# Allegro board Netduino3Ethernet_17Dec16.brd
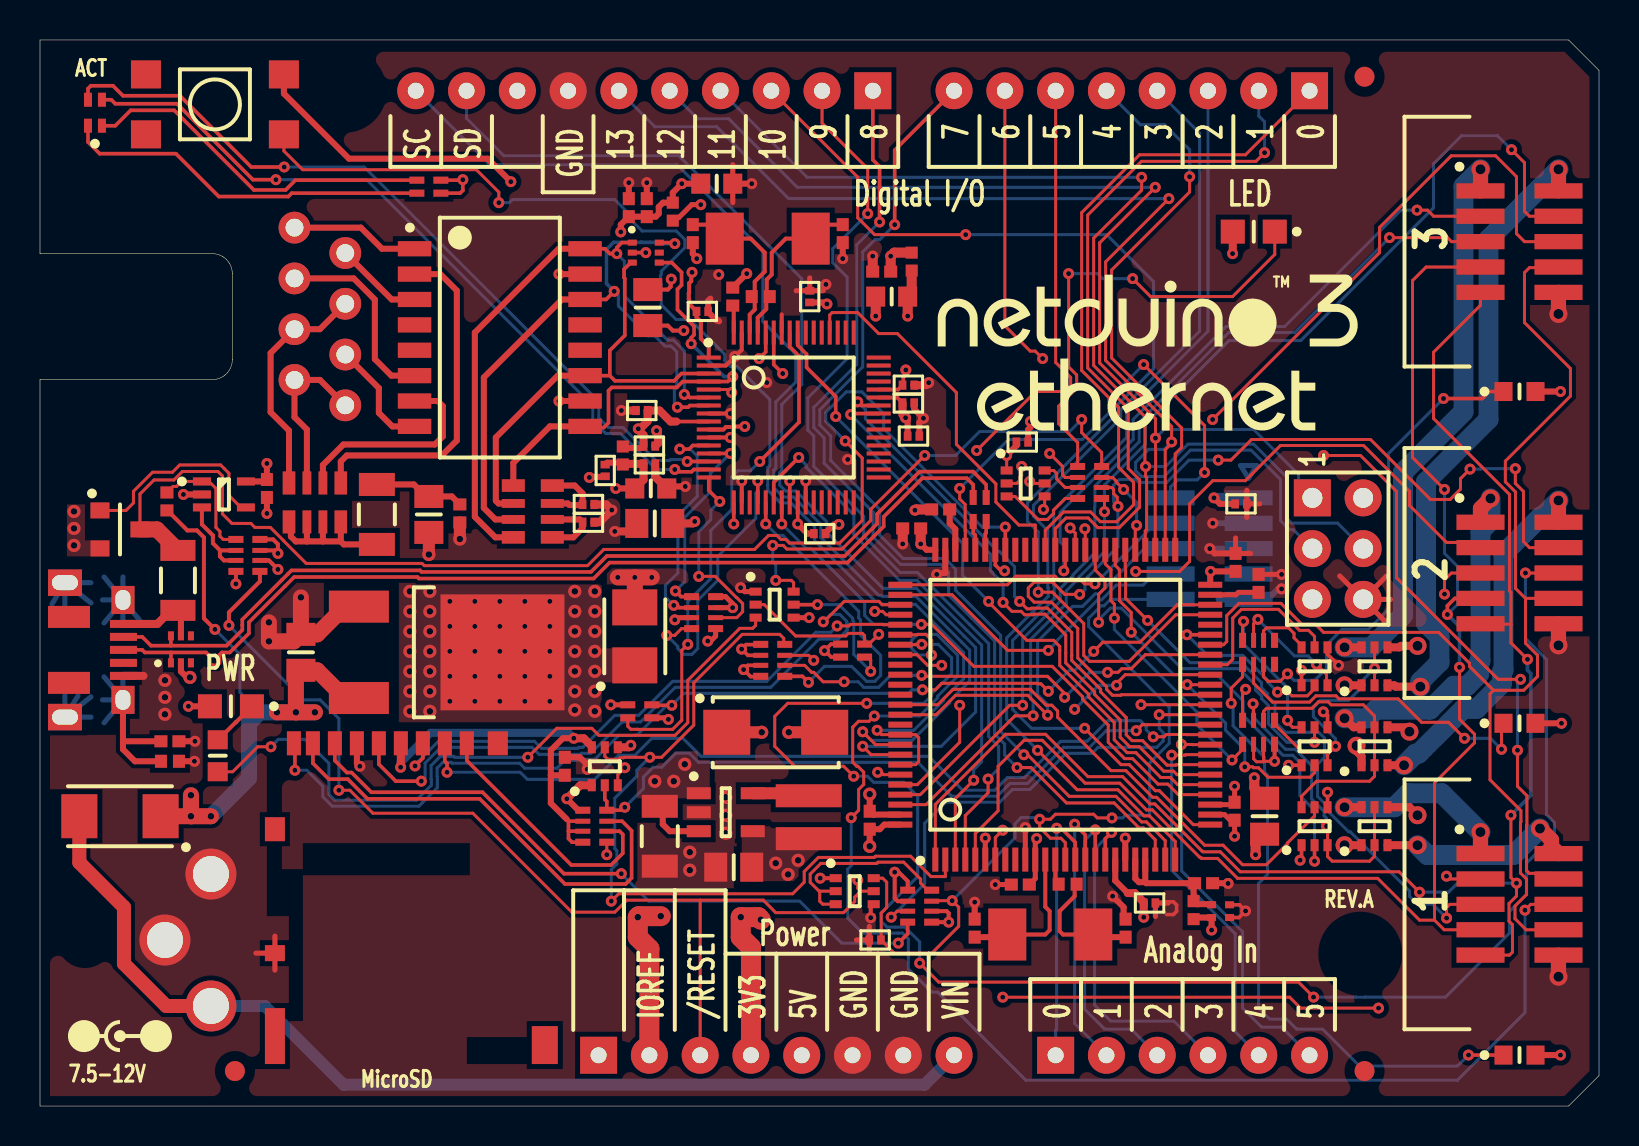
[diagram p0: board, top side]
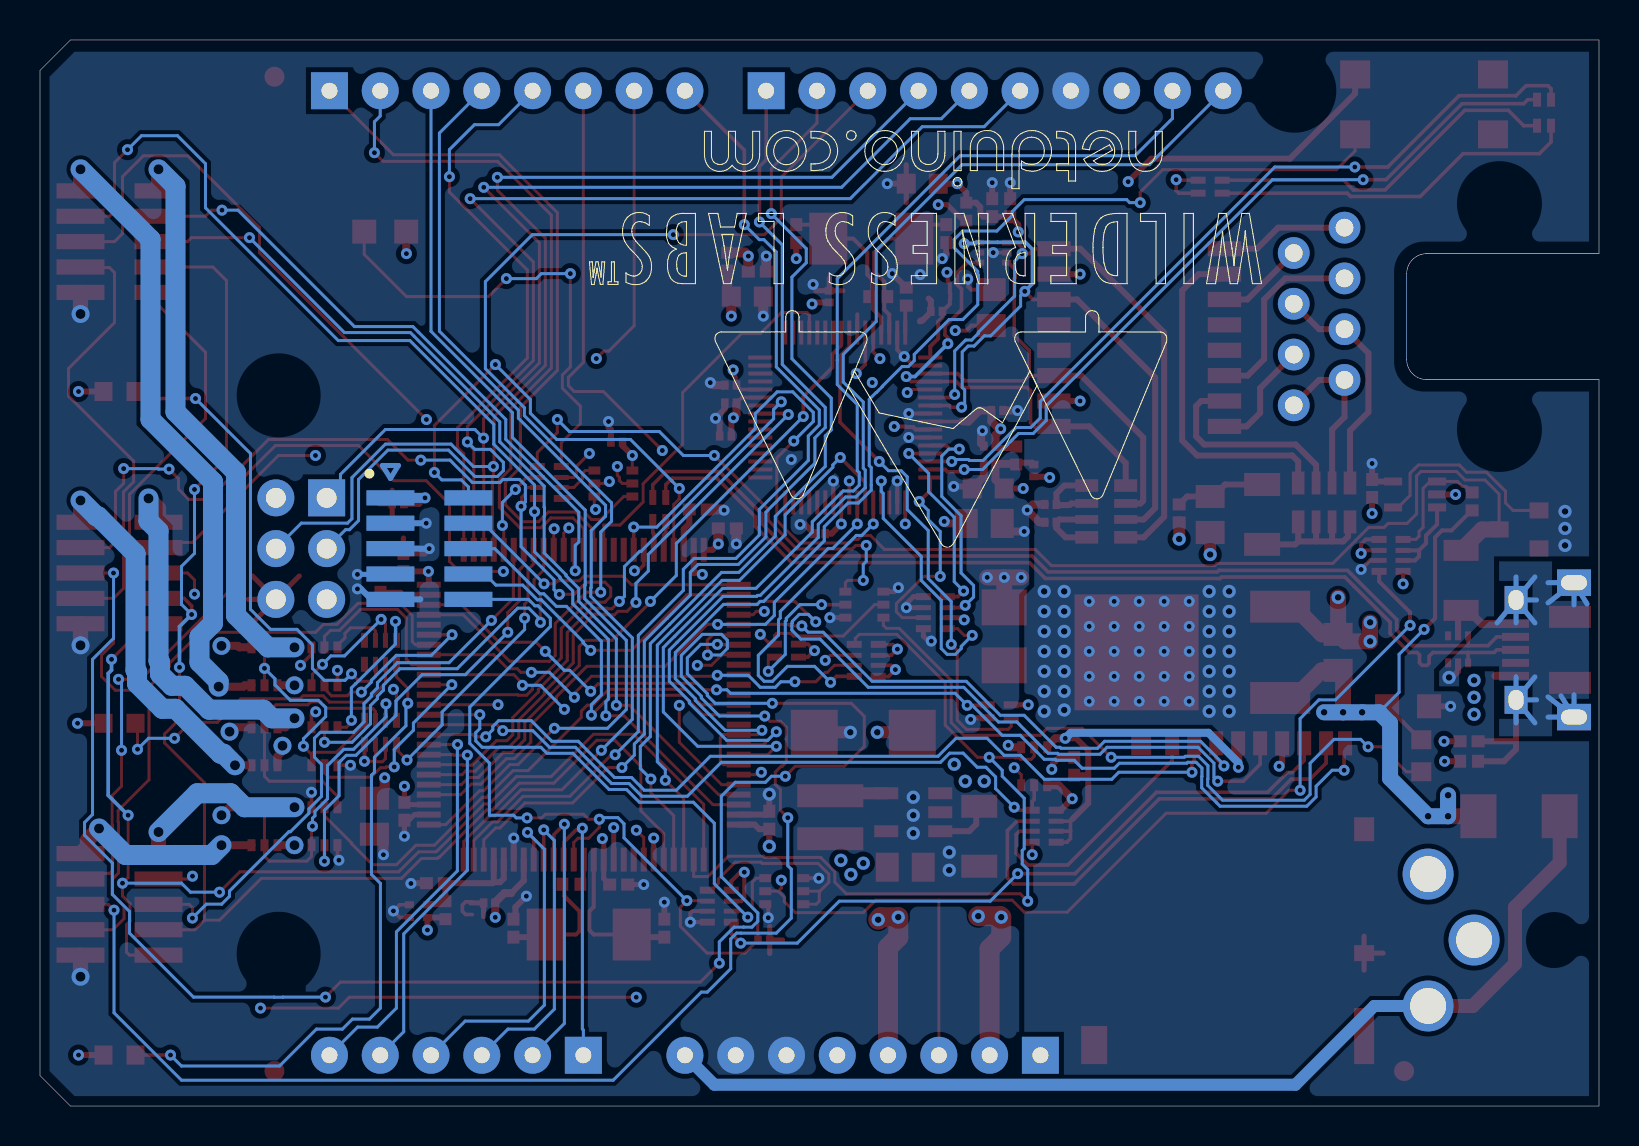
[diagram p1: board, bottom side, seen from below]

Outline 77.98 x 53.34 mm; copper layers: TOP, L2-GND, L3-PWR, BOTTOM. Coordinates in mm from the lower left corner of the outline.
Outline path: 0,53.34 0,42.65 8.62,42.65 arc(9.33,42.35) 9.62,41.65 9.62,37.35 arc(9.33,36.64) 8.62,36.35 0,36.35 0,0 76.45,0 77.98,1.52 77.98,51.82 76.45,53.34 0,53.34

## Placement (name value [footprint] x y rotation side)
C1  22uF  [CAPC3216X180N]  31 13.5 270 top
C2  10uF  [CAPC2012X125N]  13.05 22.7 90 top
C4  22uF  [CAPC2012X125N]  34.7 11.95 180 top
C5  0.1uF  [CAPC1005X55N]  58.2 11.15 0 top
C6  0.1uF  [CAPC1005X55N]  11.35 30.9 270 top
C7  1uF  [GNM1M2]  59.05 9.75 0 top
C9  0.1uF  [CAP-0201]  55.5 10.16 0 top
C10  0.1uF  [CAPC1005X55N]  49.03 11.08 180 top
C11  0.1uF  [CAPC1005X55N]  59.75 14.75 270 top
C12  0.1uF  [CAPC1005X55N]  59.8 27.2 90 top
C13  0.1uF  [CAPC1005X55N]  43.6 28.9 180 top
C14  0.1uF  [CAPC1005X55N]  41.5 14.3 90 top
C16  2.2uF  [CAPC1005X55N]  45.05 29.85 180 top
C17  2.2uF  [CAPC1005X55N]  60.95 26.15 90 top
C18  18pF  [CAPC1005X55N]  46.75 8.9 90 top
C19  18pF  [CAPC1005X55N]  54.3 8.9 90 top
C20  4.7nF  [CAPC1005X55N]  6.5 18.25 180 top
C21  100uF  [CAPMP6032X280N]  36.8 18.7 0 top
C22  0.1uF  [CAPC1005X55N]  26.25 17 90 top
C23  22uF  [CAPC2012X125N]  30.75 29.15 180 top
C24  0.1uF  [CAP-0201]  30.1 34.8 180 top
C25  22uF  [CAPC2012X125N]  30.4 39.95 90 top
C26  0.1uF  [CAP-0201]  33.13 39.76 0 top
C27  4.7uF  [CAPC1608X90N]  33.85 46.15 0 top
C28  1uF  [CAPC1005X55N]  30.35 44.95 90 top
C29  0.1uF  [CAPC1005X55N]  29.45 44.95 90 top
C30  0.1uF  [CAP-0201]  38.5 40.5 90 top
C31  0.1uF  [CAP-0201]  43.43 35.18 0 top
C32  0.1uF  [CAP-0201]  30.48 32.13 0 top
C33  0.1uF  [CAPC1005X55N]  42.1 41.75 180 top
C34  4.7uF  [CAPC1608X90N]  42.6 40.5 180 top
C35  0.1uF  [CAP-0201]  28.27 31.8 270 top
C36  4.7uF  [CAPC1608X90N]  30.55 30.9 0 top
C37  18pF  [CAPC1005X55N]  40.15 43.65 270 top
C38  18pF  [CAPC1005X55N]  32.65 43.65 270 top
C39  0.1uF  [CAP-0201]  27.43 30.1 0 top
C40  1nF  [CAPC3216X180N]  16.85 29.6 90 top
C41  0.1uF  [CAPC2012X125N]  19.45 29.6 90 top
C42  22uF  [CAPC2012X125N]  61.25 14.5 270 top
C43  47uF  [F931A476MBA]  29.75 23.5 90 top
C44  0.1uF  [CAP-0201]  41.77 8.31 180 top
C45  0.1uF  [CAP-0201]  60.07 30.13 0 top
C46  0.1uF  [CAP-0201]  49.13 33.22 0 top
C47  0.1uF  [CAP-0201]  39 28.64 0 top
C48  0.1uF  [CAP-0201]  43.43 36.07 0 top
C49  0.1uF  [CAP-0201]  43.69 33.52 0 top
C50  0.1uF  [CAP-0201]  30.48 33.02 0 top
C51  0.1uF  [CAP-0201]  27.43 29.21 0 top
D1  WHITE  [LEDC2012X110N]  9.55 20 180 top
D2  BLUE  [LEDC2012X110N]  60.71 43.75 180 top
D3  SS15E-TP  [SS15-TP]  4 14.5 180 top
D4  -  [SP3003-04XTG]  7.05 22.85 90 top
D5  BLUE  [LEDC1608X80N]  74 2.55 0 top
D6  BLUE  [LEDC1608X80N]  74 19.15 0 top
D7  BLUE  [LEDC1608X80N]  74 35.75 0 top
D8  -  [SP3003-04XTG]  30.3 42.7 0 top
D9  GREEN  [LTST-C295]  2.75 49.7 90 top
F1  MF-NSMF075-2  [RESC3216X100N]  6.9 26.3 90 top
F2  -  [FID_1-00_X_2-00]  9.75 1.75 0 top
F3  -  [FID_1-00_X_2-00]  66.25 1.75 0 top
F4  -  [FID_1-00_X_2-00]  66.25 51.5 0 top
J1  -  [ADC-043A-1]  8.55 8.31 90 top
J2  HDR100IMP08F-G-V-TH-BLUE  [HDR100IMP08F-G-V-TH]  63.5 50.8 180 top
J3  HDR100IMP08F-G-V-TH-BLUE  [HDR100IMP10F-G-V-TH]  41.66 50.8 180 top
J4  HDR100IMP08F-G-V-TH-BLUE  [HDR100IMP06F-G-V-TH]  50.8 2.54 0 top
J5  -  [DX4R005JJ2R1800]  0 22.82 270 top
J6  HDR100IMP08F-G-V-TH-BLUE  [HDR100IMP08F-G-V-TH]  27.94 2.54 0 top
J7  -  [67996-206HLF]  63.64 30.43 270 top
J8  -  [MINI_JTAG_SMD]  58.5 27.89 180 bottom
J9  DM3AT-SF-PEJM5  [DM3AT-SF-PEJ]  21.35 17.55 0 top
J10  HDR050IDC10MS2-G-V-SM-BLUE  [20021521-00010T1LF]  74 10.09 0 top
J11  HDR050IDC10MS2-G-V-SM-BLUE  [20021521-00010T1LF]  74 26.67 0 top
J12  HDR050IDC10MS2-G-V-SM-BLUE  [20021521-00010T1LF]  74 43.25 0 top
J13  -  [44661-0002]  0 39.5 270 top
L1  2.2uH  [LQH3NPN2R2NM0L]  38.45 14.45 270 top
L2  BEAD FERRITE/SM  [INDC1005X55N]  57.7 9.8 270 top
L3  BEAD FERRITE/SM  [INDC1005X55N]  31.65 44.75 90 top
L4  BEAD FERRITE/SM  [INDC1005X55N]  43.6 42.25 270 top
L5  BEAD FERRITE/SM  [INDC1005X55N]  29.15 32.55 90 top
MT1  -  [MTG320H420NP_720KO]  15.24 50.8 0 top
MT2  -  [MTG320H420NP_720KO]  66.04 35.56 0 top
MT3  -  [MTG320H420NP_720KO]  66.04 7.62 0 top
NOREF  -  []  44.9 38 0 top
NOREF#2  -  []  0 0 90 top
NOREF#3  -  []  4 3.5 0 top
NOREF#4  -  []  0 53.34 0 top
Q1  -  [MUN5215DW1T1G]  36.74 25.09 0 top
Q2  -  [MUN5215DW1T1G]  40.75 10.75 0 top
Q3  -  [NTR4101PT1G]  4 28.85 0 top
Q4  -  [NTJD4152PT1G]  28.25 17 90 top
Q5  -  [NTJD4152PT1G]  66.75 14 90 top
Q6  -  [MUN5215DW1T1G]  63.75 14 90 top
Q7  -  [NTJD4152PT1G]  66.75 18 90 top
Q8  -  [NTJD4152PT1G]  49.3 31.15 0 top
Q9  -  [NTJD4152PT1G]  66.75 22 90 top
Q10  -  [MUN5215DW1T1G]  63.75 18 90 top
Q11  -  [MUN5215DW1T1G]  63.75 22 90 top
R1  1K  [RESCAV50P80X160X60-8N]  52.5 31.2 0 top
R3  1.5K  [CAPC1608X90N]  8.89 17.53 270 top
R4  10K  [RESCAV50P80X160X60-8N]  10.4 27.55 0 top
R5  10K  [RESCAV50P80X160X60-8N]  44 10 0 top
R6  15.4K  [RESC1005X40AN]  6.35 30.25 90 top
R7  390  [RESC1005X40AN]  51.4 11.1 180 top
R8  100K  [EXB24V]  40.64 22.79 0 top
R9  22  [EXB24V]  47 29.85 270 top
R10  1M  [RESC1005X40AN]  6.5 17.25 180 top
R11  10K  [RESCAV50P80X160X60-8N]  27.75 14 0 top
R12  10K  [RESCAV50P80X160X60-8N]  60.95 18.7 90 top
R13  10K  [EXB24V]  30 19.75 0 top
R14  10K  [RESCAV50P80X160X60-8N]  36.65 22.3 0 top
R15  680  [RESCAV50P80X160X60-8N]  60.95 22.7 90 top
R16  1M  [RESC1005X40AN]  36.05 40.5 180 top
R17  49.9  [CRA06S]  24.65 29.75 0 top
R18  75  [CRA06S]  13.75 30.2 270 top
R19  10K  [RESCAV50P80X160X60-8N]  33.19 24.69 0 top
R20  1M  [RESC1005X40AN]  21 29.65 90 top
R21  12.1K  [RESC1005X40AN]  34.65 40.5 90 top
R22  1.5K  [EXB24V]  19.45 46 180 top
SW1  -  [TSXH-2GL]  8.75 50.12 0 top
T1  HX1198NLT  [HX1198NL]  23 38.45 0 top
U1  LM3671MF-3.3/NOPB  [LM3671MF]  34.3 14.7 0 top
U2  -  [TLV1117-50IKVURG3]  15.95 22.7 0 top
U3  -  [LMV321IDCKR]  9.2 30.6 0 top
U4  STM32F427  [STM32F427VIT6]  50.78 20.08 90 top
U5  -  [AX88796CLF]  37.7 34.45 0 top
Y1  25.00MHz  [ABM7]  50.53 8.58 180 top
Y2  25.00MHz  [ABM7]  36.4 43.4 0 top

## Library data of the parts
C1 C2 C4-C6 C9-C14 C16-C51 = C
C7 = GNM1M2
D1 = LED_2
D2 D5-D7 = LED_1
D3 = D05AZ75_0
D4 D8 = HEADER 6_0
D9 = LED0603_GREEN_STR_1
F1 = FUSE
F2-F4 MT1-MT3 = MOUNT_HOLE
J1 = HEADER 3
J2 J6 = HEADER 8
J3 = HEADER 10
J4 = HEADER 6
J5 = HEADER 11_0
J7 = HEADER 6_1
J8 J10-J12 = HEADER 10_2
J9 = HEADER 10_4
J13 = CONN_FPC10P_2
L1 = L
L2-L5 = BEAD FERRITE/SM
Q1 Q2 = MUN5215DW1T1G_3
Q3 = NDF0610/TO_1
Q4 Q5 Q7-Q9 = NTJD4152PT1G
Q6 Q10 Q11 = MUN5215DW1T1G_0
R1 R4 R5 R11 R12 R14 R15 R17-R19 = RESCAV50P80X160X60-8N
R3 R6 R7 R10 R16 R20 R21 = R
R8 R9 R13 R22 = EXB24V
SW1 = SW PUSHBUTTON-SPST-2_0
T1 = HX1198NLT_0
U1 = HEADER 5_0
U2 = LM7805/TO_2
U3 = LMV321/SO
U4 = STM32F427_0
U5 = AX88796CLF_1
Y1 Y2 = CRYSTAL

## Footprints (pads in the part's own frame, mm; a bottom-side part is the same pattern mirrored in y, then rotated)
44661-0002
  round 0 hole 3.25 unplated: (-5.65,4.98) (5.65,4.98)
  round 1.59 hole 0.89: 1(-4.45,12.73) 2(-3.18,15.27) 3(-1.91,12.73) 4(-0.64,15.27) 5(0.63,12.73) 6(1.9,15.27) 7(3.17,12.73) 8(4.44,15.27)
67996-206HLF
  rect 1.85x1.85 hole 1: 1(0,0)
  round 1.85 hole 1: 2(0,2.54) 3(2.54,0) 4(2.54,2.54) 5(5.08,0) 6(5.08,2.54)
20021521-00010T1LF
  rect 2.4x0.76 smd: 1(-1.95,2.54) 2(1.95,2.54) 3(-1.95,1.27) 4(1.95,1.27) 5(-1.95,0) 6(1.95,0) 7(-1.95,-1.27) 8(1.95,-1.27) 9(-1.95,-2.54) 10(1.95,-2.54)
ABM7
  rect 1.9x2.6 smd: 1(-2.15,0) 2(2.15,0)
ADC-043A-1
  round 0 hole 2.4 unplated: (0,6.3)
  round 2.55 hole 1.8: 1(-3.3,0) 2(0,2.3) 3(3.3,0)
AX88796CLF
  rect 1.2x0.2 smd: 1(-4.25,3) 2(-4.25,2.6) 3(-4.25,2.2) 4(-4.25,1.8) 5(-4.25,1.4) 6(-4.25,1) 7(-4.25,0.6) 8(-4.25,0.2) 9(-4.25,-0.2) 10(-4.25,-0.6) 11(-4.25,-1) 12(-4.25,-1.4) 13(-4.25,-1.8) 14(-4.25,-2.2) 15(-4.25,-2.6) 16(-4.25,-3) 33(4.25,-3) 34(4.25,-2.6) 35(4.25,-2.2) 36(4.25,-1.8) 37(4.25,-1.4) 38(4.25,-1) 39(4.25,-0.6) 40(4.25,-0.2) 41(4.25,0.2) 42(4.25,0.6) 43(4.25,1) 44(4.25,1.4) 45(4.25,1.8) 46(4.25,2.2) 47(4.25,2.6) 48(4.25,3)
  rect 0.2x1.2 smd: 17(-3,-4.25) 18(-2.6,-4.25) 19(-2.2,-4.25) 20(-1.8,-4.25) 21(-1.4,-4.25) 22(-1,-4.25) 23(-0.6,-4.25) 24(-0.2,-4.25) 25(0.2,-4.25) 26(0.6,-4.25) 27(1,-4.25) 28(1.4,-4.25) 29(1.8,-4.25) 30(2.2,-4.25) 31(2.6,-4.25) 32(3,-4.25) 49(3,4.25) 50(2.6,4.25) 51(2.2,4.25) 52(1.8,4.25) 53(1.4,4.25) 54(1,4.25) 55(0.6,4.25) 56(0.2,4.25) 57(-0.2,4.25) 58(-0.6,4.25) 59(-1,4.25) 60(-1.4,4.25) 61(-1.8,4.25) 62(-2.2,4.25) 63(-2.6,4.25) 64(-3,4.25)
CAP-0201
  rect 0.381x0.457 smd: 1(-0.292,0) 2(0.292,0)
CAPC1005X55N
  rect 0.65x0.6 smd: 1(-0.45,0) 2(0.45,0)
CAPC1608X90N
  rect 0.95x1 smd: 1(-0.8,0) 2(0.8,0)
CAPC2012X125N
  rect 1.15x1.45 smd: 1(-0.9,0) 2(0.9,0)
CAPC3216X180N
  rect 1.15x1.8 smd: 1(-1.5,0) 2(1.5,0)
CAPMP6032X280N
  rect 2.35x2.25 smd: 1(-2.45,0) 2(2.45,0)
CRA06S
  rect 1.15x0.63 smd: 1(-0.975,1.295) 4(-0.975,-1.295) 5(0.975,-1.295) 8(0.975,1.295)
  rect 1.15x0.44 smd: 2(-0.975,0.4) 3(-0.975,-0.4) 6(0.975,-0.4) 7(0.975,0.4)
DM3AT-SF-PEJ
  rect 0.7x1.2 smd: 1(0,0.6) 2(-1.1,0.6) 3(-2.2,0.6) 4(-3.3,0.6) 5(-4.4,0.6) 6(-5.5,0.6) 7(-6.6,0.6) 8(-7.7,0.6) 9(-8.65,0.6)
  rect 1x0.8 smd: 10(-9.6,-9.9)
  rect 1x1.2 smd: 11(-9.6,-3.7) 14(1.55,0.6)
  rect 1x2.8 smd: 12(-9.6,-14.05)
  rect 1.3x1.9 smd: 13(3.9,-14.5)
DX4R005JJ2R1800
  rect 0.4x1.35 smd: 1(-1.3,4.175) 2(-0.65,4.175) 3(0,4.175) 4(0.65,4.175) 5(1.3,4.175)
  rect 1.4x1.15 hole 1x0.75: 6(-2.5,4.15) 7(2.5,4.15)
  rect 1.325x1.7 hole 0.75x1.3: 8(-3.362,1.25) 11(3.362,1.25)
  rect 1.1x2.1 smd: 9(-1.65,1.45) 10(1.65,1.45)
EXB24V
  rect 0.75x0.35 smd: 1(-0.6,0.325) 2(-0.6,-0.325) 3(0.6,-0.325) 4(0.6,0.325)
F931A476MBA
  rect 1.8x2.25 smd: 1(-1.45,0) 2(1.45,0)
FID_1-00_X_2-00
  round 1 smd: 1(0,0)
GNM1M2
  rect 0.45x0.35 smd: 1(-0.45,0.32) 2(-0.45,-0.32) 3(0.45,-0.32) 4(0.45,0.32)
HDR100IMP06F-G-V-TH
  rect 1.85x1.85 hole 0.8: 1(0,0)
  round 1.85 hole 0.8: 2(2.54,0) 3(5.08,0) 4(7.62,0) 5(10.16,0) 6(12.7,0)
HDR100IMP08F-G-V-TH
  rect 1.85x1.85 hole 0.8: 1(0,0)
  round 1.85 hole 0.8: 2(2.54,0) 3(5.08,0) 4(7.62,0) 5(10.16,0) 6(12.7,0) 7(15.24,0) 8(17.78,0)
HDR100IMP10F-G-V-TH
  rect 1.85x1.85 hole 0.8: 1(0,0)
  round 1.85 hole 0.8: 2(2.54,0) 3(5.08,0) 4(7.62,0) 5(10.16,0) 6(12.7,0) 7(15.24,0) 8(17.78,0) 9(20.32,0) 10(22.86,0)
HX1198NL
  rect 1.67x0.76 smd: 1(-4.265,4.445) 2(-4.265,3.175) 3(-4.265,1.905) 4(-4.265,0.635) 5(-4.265,-0.635) 6(-4.265,-1.905) 7(-4.265,-3.175) 8(-4.265,-4.445) 9(4.265,-4.445) 10(4.265,-3.175) 11(4.265,-1.905) 12(4.265,-0.635) 13(4.265,0.635) 14(4.265,1.905) 15(4.265,3.175) 16(4.265,4.445)
INDC1005X55N
  rect 0.6x0.6 smd: 1(-0.45,0) 2(0.45,0)
LEDC1608X80N
  rect 0.899x0.95 smd: A(0.8,0) C(-0.8,0)
LEDC2012X110N
  rect 1.2x1.2 smd: A(1.05,0) C(-1.05,0)
LM3671MF
  rect 1.2x0.6 smd: 1(-1.35,0.95) 2(-1.35,0) 3(-1.35,-0.95) 4(1.35,-0.95) 5(1.35,0.95)
LMV321IDCKR
  rect 0.9x0.4 smd: 1(-1.1,0.65) 2(-1.1,0) 3(-1.1,-0.65) 4(1.1,-0.65) 5(1.1,0.65)
LQH3NPN2R2NM0L
  rect 1.15x3.3 smd: 1(-1.075,0) 2(1.075,0)
LTST-C295
  rect 0.7x0.4 smd: 1(-0.65,0.35) 2(-0.65,-0.35) 3(0.65,0.35) 4(0.65,-0.35)
MINI_JTAG_SMD
  rect 2.4x0.76 smd: 1(-1.95,2.54) 2(1.95,2.54) 3(-1.95,1.27) 4(1.95,1.27) 5(-1.95,0) 6(1.95,0) 7(-1.95,-1.27) 8(1.95,-1.27) 9(-1.95,-2.54) 10(1.95,-2.54)
MTG320H420NP_720KO
  round 0 hole 3.2 unplated: (0,0)
MUN5215DW1T1G
  rect 0.6x0.4 smd: 1(-0.95,0.65) 2(-0.95,0) 3(-0.95,-0.65) 4(0.95,-0.65) 5(0.95,0) 6(0.95,0.65)
NTJD4152PT1G
  rect 0.6x0.4 smd: 1(-0.95,0.65) 2(-0.95,0) 3(-0.95,-0.65) 4(0.95,-0.65) 5(0.95,0) 6(0.95,0.65)
NTR4101PT1G
  rect 0.95x0.8 smd: 1(-1,0.95) 2(-1,-0.95) 3(1,0)
RESC1005X40AN
  rect 0.6x0.65 smd: 1(-0.45,0) 2(0.45,0)
RESC3216X100N
  rect 1.05x1.75 smd: 1(-1.5,0) 2(1.5,0)
RESCAV50P80X160X60-8N
  rect 0.75x0.35 smd: 1(-0.6,0.8) 4(-0.6,-0.8) 5(0.6,-0.8) 8(0.6,0.8)
  rect 0.75x0.25 smd: 2(-0.6,0.25) 3(-0.6,-0.25) 6(0.6,-0.25) 7(0.6,0.25)
SP3003-04XTG
  rect 0.45x0.3 smd: 1(-0.675,0.5) 2(-0.675,0) 3(-0.675,-0.5) 4(0.675,-0.5) 5(0.675,0) 6(0.675,0.5)
SS15-TP
  rect 1.8x2.2 smd: A(2.032,0) C(-2.032,0)
STM32F427VIT6
  rect 1.2x0.3 smd: 1(-7.75,6) 2(-7.75,5.5) 3(-7.75,5) 4(-7.75,4.5) 5(-7.75,4) 6(-7.75,3.5) 7(-7.75,3) 8(-7.75,2.5) 9(-7.75,2) 10(-7.75,1.5) 11(-7.75,1) 12(-7.75,0.5) 13(-7.75,0) 14(-7.75,-0.5) 15(-7.75,-1) 16(-7.75,-1.5) 17(-7.75,-2) 18(-7.75,-2.5) 19(-7.75,-3) 20(-7.75,-3.5) 21(-7.75,-4) 22(-7.75,-4.5) 23(-7.75,-5) 24(-7.75,-5.5) 25(-7.75,-6) 51(7.75,-6) 52(7.75,-5.5) 53(7.75,-5) 54(7.75,-4.5) 55(7.75,-4) 56(7.75,-3.5) 57(7.75,-3) 58(7.75,-2.5) 59(7.75,-2) 60(7.75,-1.5) 61(7.75,-1) 62(7.75,-0.5) 63(7.75,0) 64(7.75,0.5) 65(7.75,1) 66(7.75,1.5) 67(7.75,2) 68(7.75,2.5) 69(7.75,3) 70(7.75,3.5) 71(7.75,4) 72(7.75,4.5) 73(7.75,5) 74(7.75,5.5) 75(7.75,6)
  rect 0.3x1.2 smd: 26(-6,-7.75) 27(-5.5,-7.75) 28(-5,-7.75) 29(-4.5,-7.75) 30(-4,-7.75) 31(-3.5,-7.75) 32(-3,-7.75) 33(-2.5,-7.75) 34(-2,-7.75) 35(-1.5,-7.75) 36(-1,-7.75) 37(-0.5,-7.75) 38(0,-7.75) 39(0.5,-7.75) 40(1,-7.75) 41(1.5,-7.75) 42(2,-7.75) 43(2.5,-7.75) 44(3,-7.75) 45(3.5,-7.75) 46(4,-7.75) 47(4.5,-7.75) 48(5,-7.75) 49(5.5,-7.75) 50(6,-7.75) 76(6,7.75) 77(5.5,7.75) 78(5,7.75) 79(4.5,7.75) 80(4,7.75) 81(3.5,7.75) 82(3,7.75) 83(2.5,7.75) 84(2,7.75) 85(1.5,7.75) 86(1,7.75) 87(0.5,7.75) 88(0,7.75) 89(-0.5,7.75) 90(-1,7.75) 91(-1.5,7.75) 92(-2,7.75) 93(-2.5,7.75) 94(-3,7.75) 95(-3.5,7.75) 96(-4,7.75) 97(-4.5,7.75) 98(-5,7.75) 99(-5.5,7.75) 100(-6,7.75)
TLV1117-50IKVURG3
  rect 3x1.6 smd: 1(0,2.286) 3(0,-2.286)
  rect 6.2x5.8 smd: 4(7.18,0)
TSXH-2GL
  rect 1.5x1.4 smd: 1(-3.45,1.5) 2(3.45,1.5) 3(-3.45,-1.5) 4(3.45,-1.5)

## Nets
3V3_GOPORT1: J10.1(3V3) Q5.6(DRAIN)
3V3_GOPORT2: J11.1(3V3) Q7.6(DRAIN)
3V3_GOPORT3: J12.1(3V3) Q9.6(DRAIN)
5V_GOPORT1: J10.2(5V) Q5.3(DRAIN)
5V_GOPORT2: J11.2(5V) Q7.3(DRAIN)
5V_GOPORT3: J12.2(5V) Q9.3(DRAIN)
+3.3V: C4.1 C7.2(1) C9.1 C10.1 C11.1 C12.1 C13.1 C14.1 C21.1 C23.1 C33.1 C42.1 C45.1 C46.1 J6.2 J6.4 J8.1(VCC) L1.2 L2.2 L3.1 L4.1 Q4.1(SOURCE) Q4.4(SOURCE) Q5.1(SOURCE) Q7.1(SOURCE) Q8.1(SOURCE) Q8.4(SOURCE) Q9.1(SOURCE) R4.4(1) R5.1 R5.2(1) R8.1 R8.2(1) R11.1 R13.1 R14.1 R14.2(1) R14.3(1) R14.4(1) R19.3(1) R22.1 R22.2(1) SW1.2 U1.4(FB) U4.6(VBAT) U4.11(VDD1) U4.19(VDD2) U4.28(VDD3) U4.50(VDD4) U4.75(VDD5) U4.100(VDD6) U5.10(VCC3R3)
+3V3_MICROSD: C22.1 J9.4(VDD) Q4.6(DRAIN) R11.2(1) R11.3(1) R11.4(1)
+5.0V: C1.1 C6.1 C43.1 D1.A(ANODE) D2.A(ANODE) D5.A(ANODE) D6.A(ANODE) D7.A(ANODE) J6.5 J7.2(VTG) Q3.2(SOURCE) Q5.4(SOURCE) Q7.4(SOURCE) Q9.4(SOURCE) R4.6(2) R12.2(1) R12.3(1) R12.4(1) U1.1(VIN) U1.3(EN) U2.4(VOUT) U3.5(+VCC)
+VIN: D3.A(1) J1.1 J6.8
+VIN_PROTECTED: C2.1 D3.C(2) R6.1 U2.3(VIN)
GND: C1.2 C2.2 C4.2 C5.2 C6.2 C7.3 C7.4(3) C9.2 C10.2 C11.2 C12.2 C13.2 C14.2 C16.2 C17.2 C18.2 C19.2 C20.1 C21.2 C22.2 C23.2 C24.2 C25.2 C26.2 C27.2 C28.2 C29.2 C30.2 C31.2 C32.2 C33.2 C34.2 C35.2 C36.2 C37.2 C38.2 C39.2 C41.1 C42.2 C43.2 C44.2 C45.2 C46.2 C47.2 C48.2 C49.2 C50.2 C51.2 D8.2(GND) J1.2 J1.3 J3.7 J5.5(GND) J6.6 J6.7 J7.6(GND) J8.3(GND1) J8.5(GND2) J8.7(GND3) J8.9(GND4) J9.6(VSS) J9.10(SW_GND) J10.10(GND) J11.10(GND) J12.10(GND) Q1.1(E) Q1.4(E) Q2.1(E) Q2.4(E) Q6.1(E) Q6.4(E) Q10.1(E) Q10.4(E) Q11.1(E) Q11.4(E) R4.7(2) R4.8(2) R5.5(2) R5.6(2) R10.1 R11.5(2) R12.8(2) R13.3(2) R19.5(2) R19.7(2) R19.8(2) R20.1 R21.2 U1.2(GND) U2.1(GND) U3.2(-VCC) U4.10(VSS1) U4.20(VSSA) U4.27(VSS2) U4.74(VSS3) U4.99(VSS4) U5.2(GND3A3) U5.8(GND18A#8) U5.11(GND3R3) U5.18(GND#18) U5.26(GND#26) U5.58(GND#58) U5.63(GND18A#63)
VCC3A3: C26.1 C27.1 C28.1 C29.1 L3.2 T1.10(CT_R) T1.15(CT_T) U5.1(VCC3A3)
VCC18: C24.1 C25.1 C30.1 C31.1 C49.1 C50.1 L5.2 U5.9(V18F) U5.24(VCCK#24) U5.43(VCCK#43) U5.59(VCCK#59)
VCC18A: C32.1 C35.1 C36.1 L5.1 U5.5(VCC18A#5) U5.60(VCC18A#60)
VCCIO: C34.1 C47.1 C48.1 L4.2 U5.25(VCCIO#25) U5.44(VCCIO#44)
VDDA: C5.1 C7.1 L2.1 U4.21(VREF+) U4.22(VDDA)
VIN_COMP: R4.1 R6.2 U3.1(+VIN)
VIN_COMP_LOGIC: Q3.1(GATE) U3.4(OUT)
VIN_REF: R4.2(1) R4.3(1) U3.3(-VIN)
/AX_CS: U4.65(PC8) U5.52(SSN)
/AX_INT: U4.29(PA4) U5.23(IRQ)
/AX_RESET: R5.3(1) U4.37(PB2) U5.17(RSTN)
/ENABLE_UART_TX_PULLUP_GOPORT1: Q4.5(GATE) R14.8(2) U4.2(PE3)
/ENABLE_UART_TX_PULLUP_GOPORT2: Q8.2(GATE) R14.7(2) U4.41(PE10)
/ENABLE_UART_TX_PULLUP_GOPORT3: Q8.5(GATE) R14.6(2) U4.43(PE12)
/EXTERNAL_RESET: J6.3 J7.5(R\E\S\E\T\) Q2.5(B) R4.5(2)
/INT_GOPORT1: J10.3(GIPO) U4.60(PD13)
/INT_GOPORT2: J11.3(GIPO) U4.61(PD14)
/INT_GOPORT3: J12.3(GIPO) U4.62(PD15)
/LINK_ACT: D9.3(CATHODE_GREEN) U5.14(I_LK/ACT)
/MICRO_SD_CARD_INSERTED: J9.9(C\A\R\D\_\I\N\_\S\W\) R13.4(2) U4.48(PB11)
/MICROSD_CS: J9.2(C\S\) U4.35(PB0)
/PWR_CTRL_GOPORT1: Q5.2(GATE) Q5.5(GATE) Q6.3(C) R12.7(2)
/PWR_CTRL_GOPORT2: Q6.6(C) Q7.2(GATE) Q7.5(GATE) R12.6(2)
/PWR_CTRL_GOPORT3: Q9.2(GATE) Q9.5(GATE) Q10.3(C) R12.5(2)
/PWR_CTRL_MICROSD: Q4.2(GATE) R11.8(2) U4.36(PB1)
/RESET_MCU: C44.1 J8.10(NRST) Q2.6(C) R5.7(2) U4.14(NRST)
/SPEED: D9.4(CATHODE_YELLOW) U5.15(I_SPEED)
/SPI_CS_GOPORT1: J10.6(SPI_CS) U4.81(PD0)
/SPI_CS_GOPORT2: J11.6(SPI_CS) U4.82(PD1)
/SPI_CS_GOPORT3: J12.6(SPI_CS) U4.83(PD2)
A0: J4.1 U4.15(PC0)
A1: J4.2 U4.16(PC1)
A2: J4.3 U4.17(PC2)
A3: J4.4 U4.18(PC3)
A4: J4.5 U4.33(PC4)
A5: J4.6 U4.34(PC5)
AX_MISO: U4.31(PA6) U5.41(MISO)
AX_MOSI: U4.32(PA7) U5.42(MOSI)
AX_SCK: U4.30(PA5) U5.56(SPI_CLK)
AX_WAKE_UP: U4.3(PE4) U5.22(PME)
CHASSIS_ETHERNET: C40.2 C41.2 R20.2
CHASSIS_USB: C20.2 D4.2(GND) J5.6(CHS1) J5.7(CHS2) J5.8(CHS3) J5.11(CHS4) R10.2
D0: J2.1 U4.64(PC7)
D1: J2.2 U4.63(PC6)
D2: J2.3 U4.26(PA3)
D3: J2.4 U4.25(PA2)
D4: J2.5 U4.51(PB12)
D5: J2.6 U4.95(PB8)
D6: J2.7 U4.96(PB9)
D7: J2.8 U4.24(PA1)
D8: J3.1 U4.23(PA0)
D9: J3.2 U4.4(PE5)
D10: J3.3 U4.47(PB10)
D11: J3.4 J7.4(MOSI) U4.54(PB15)
D12: J3.5 J7.1(MISO) U4.53(PB14)
D13: J3.6 J7.3(SCK) U4.52(PB13)
JTCK: J8.4(JTCK) U4.76(PA14)
JTDI: J8.8(JTDI) U4.77(PA15)
JTDO: J8.6(JTDO) U4.89(PB3)
JTMS: J8.2(JTMS) U4.72(PA13)
LED: Q1.2(B) R8.4(2) U4.69(PA10)
LED_GOPORT1: Q10.2(B) U4.40(PE9)
LED_GOPORT2: Q11.5(B) U4.42(PE11)
LED_GOPORT3: Q11.2(B) U4.45(PE14)
OSC_IN: C18.1 U4.12(PH0) Y1.2
OSC_OUT: R7.2 U4.13(PH1)
OTG_FS_DM: R9.4(2) U4.70(PA11)
OTG_FS_DP: R9.3(2) U4.71(PA12)
PWR_LED: Q1.5(B) R8.3(2) U4.7(PC13)
PWR_ON_GOPORT1: Q6.5(B) U4.88(PD7)
PWR_ON_GOPORT2: Q6.2(B) U4.57(PD10)
PWR_ON_GOPORT3: Q10.5(B) U4.59(PD12)
RD+: D8.3(I/O2) R17.2(1) T1.11(RD+) U5.3(TPI+)
RD-: D8.4(I/O3) R17.1 T1.9(RD-) U5.4(TPI-)
RSET_BG: R21.1 U5.64(RSET_BG)
RX+: J13.3(RX+) T1.6(RX+)
RX-: J13.6(RX-) T1.8(RX-)
SCL: J3.10 U4.92(PB6)
SDA: J3.9 U4.93(PB7)
SPI3_MISO: J9.7(DO) R5.4(1) U4.79(PC11)
SPI3_MOSI: J9.3(DI) U4.80(PC12)
SPI3_SCK: J9.5(CLK) U4.78(PC10)
SPI4_MISO: J10.8(SPI_MISO) J11.8(SPI_MISO) J12.8(SPI_MISO) U4.44(PE13)
SPI4_MOSI: J10.7(SPI_MOSI) J11.7(SPI_MOSI) J12.7(SPI_MOSI) U4.5(PE6)
SPI4_SCK: J10.9(SPI_SCK) J11.9(SPI_SCK) J12.9(SPI_SCK) U4.1(PE2)
SWITCH1: R12.1 SW1.4 U4.58(PD11) U4.91(PB5) U4.94(BOOT0)
TD+: D8.1(I/O1) R17.4(1) T1.16(TD+) U5.6(TPO+)
TD-: D8.6(I/O4) R17.3(1) T1.14(TD-) U5.7(TPO-)
TX+: J13.1(TX+) T1.1(TX+)
TX-: J13.2(TX-) T1.3(TX-)
USART3_RX_GOPORT1: J10.5(USART_RX) U4.56(PD9)
USART3_TX_GOPORT1: J10.4(USART_TX) R1.7(2) U4.55(PD8)
USART7_RX_GOPORT2: J11.5(USART_RX) U4.38(PE7)
USART7_TX_GOPORT2: J11.4(USART_TX) R1.6(2) U4.39(PE8)
USART8_RX_GOPORT3: J12.5(USART_RX) U4.97(PE0)
USART8_TX_GOPORT3: J12.4(USART_TX) R1.5(2) U4.98(PE1)
USB5V: D4.5(VCC) F1.1 J5.1(VBUS)
USB5V_F: F1.2 Q3.3(DRAIN) U4.68(PA9)
USB_D+: D4.1(I/O1) J5.3(D+) R9.2(1)
USB_D-: D4.6(I/O4) J5.2(D-) R9.1
VCAP_1: C17.1 U4.49(VCAP_1)
VCAP_2: C16.1 U4.73(VCAP_2)
XTALIN: C37.1 R16.1 U5.61(XTALIN) Y2.2
XTALOUT: C38.1 R16.2 U5.62(XTALOUT) Y2.1
N332853: Q2.2(B) Q2.3(C) R5.8(2)
N332873: L1.1 U1.5(SW)
N332891: D2.C(CATHODE) R1.1
N333149: Q1.6(C) R1.8(2)
N333173: D1.C(CATHODE) R3.1
N333175: Q1.3(C) R3.2
N333299: C19.1 R7.1 Y1.1
N333445: J9.1(NC) R11.6(2)
N333449: J9.8(RSV) R11.7(2)
N337920: Q10.6(C) R15.8(2)
N337928: D5.C(CATHODE) R15.1
N337930: Q11.3(C) R15.7(2)
N337938: D6.C(CATHODE) R15.2(1)
N337940: Q11.6(C) R15.6(2)
N337948: D7.C(CATHODE) R15.3(1)
N337960: Q4.3(DRAIN) R1.2(1)
N337994: Q8.6(DRAIN) R1.3(1)
N338028: Q8.3(DRAIN) R1.4(1)
N338320: R19.2(1) U5.12(TEST2)
N338324: R19.1 U5.13(TEST1)
N338328: R13.2(1) U5.57(TEST_CK_EN)
N338332: R19.6(2) U5.16(I_FULL/COL)
N338402: R14.5(2) U5.21(EECS/GPIO3_1)
N338408: R19.4(1) U5.20(EECK/GPIO2_1)
N338436: C51.1 R17.5(2) R17.6(2)
N338444: C39.1 R17.7(2) R17.8(2)
N338526: J13.4 J13.5 R18.4(1)
N338532: J13.7 J13.8 R18.3(1)
N338540: R18.1 T1.2(CX_T)
N338544: R18.2(1) T1.7(RX_T)
N338558: C40.1 R18.5(2) R18.6(2) R18.7(2) R18.8(2)
N3392501: D9.1(ANODE_GREEN) R22.4(2)
N3395001: D9.2(ANODE_YELLOW) R22.3(2)

Pads without a net: D4 3 4; D8 5; F2 1; F3 1; F4 1; J3 8; J5 4 9 10; J6 1; J9 11 12 13 14; R15 4 5; SW1 1 3; T1 4 5 12 13; U4 8 9 46 66 67 84 85 86 87 90; U5 19 27 28 29 30 31 32 33 34 35 36 37 38 39 40 45 46 47 48 49 50 51 53 54 55

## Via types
v1: diameter 0.55, hole 0.25, TOP to BOTTOM, 344 vias
v2: diameter 0.9, hole 0.5, TOP to BOTTOM, 21 vias
v3: diameter 0.66, hole 0.33, TOP to BOTTOM, 65 vias

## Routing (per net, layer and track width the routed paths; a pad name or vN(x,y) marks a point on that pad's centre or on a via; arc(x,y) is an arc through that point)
3V3_GOPORT1: length 9.8
  TOP w0.4: Q5.6 v2(65.25,14.95)
  TOP w0.76: J10.1 v2(72.05,13.71)
  BOTTOM w1: v2(72.05,13.71) 70.11,15.65 68.44,15.65 67.74,14.95 v2(65.25,14.95)
3V3_GOPORT2: length 19.1
  TOP w0.4: Q7.6 65.7,18.95 v2(65.25,19.4)
  TOP w0.76: v2(72.55,30.4) 72.05,29.9 J11.1
  BOTTOM w1: v2(65.25,19.4) 66.38,19.4 66.81,19.83 69.52,19.83 70.71,21.02 71.38,21.02 71.97,21.62 71.97,22.21 72.05,22.28 72.05,28.77 72.55,29.27 v2(72.55,30.4)
3V3_GOPORT3: length 29.4
  TOP w0.4: Q9.6 v2(65.25,22.95)
  TOP w0.76: J12.1 v2(72.05,46.87)
  BOTTOM w1: v2(72.05,46.87) 71.2,46.02 71.2,34.73 68.17,31.71 68.17,24.55 66.57,22.95 v2(65.25,22.95)
5V_GOPORT1: length 10
  TOP w0.4: Q5.3 v2(68.9,13.05)
  TOP w0.76: v2(75.02,13.89) 75.6,13.31 75.6,12.98 J10.2
  BOTTOM w1: v2(75.02,13.89) 73.7,12.56 69.39,12.56 v2(68.9,13.05)
5V_GOPORT2: length 18.9
  TOP w0.4: Q7.3 v2(68.22,17.05)
  TOP w0.76: v2(75.95,30.3) J11.2
  BOTTOM w1: v2(75.95,30.3) 75.15,29.5 75.07,29.5 73.2,27.64 73.2,21.81 73.12,21.73 73.12,21.14 71.86,19.88 71.2,19.88 68.95,17.63 68.81,17.63 v2(68.22,17.05)
5V_GOPORT3: length 32.1
  TOP w0.4: v2(69.04,20.98) 67.81,20.98 67.74,21.05 Q9.3
  TOP w0.76: J12.2 v2(75.95,46.87)
  BOTTOM w1: v2(75.95,46.87) 72.45,43.37 72.45,34.36 69.33,31.23 69.33,24.16 70,23.48 70,22.2 69.04,21.24 v2(69.04,20.98)
+3.3V: length 82.9
  TOP w0.15: v1(50.19,29.85) 50.19,29.89 50.25,29.89 Q8.4 ; Q8.1 v1(48.35,32.55)
  TOP w0.18: R14.4 36.04,21.49 35.54,21.49 v1(35.19,21.84) 35.41,22.05 R14.3 ; R8.1 39.57,23.11 v1(39.24,22.78) 39.36,22.66 39.38,22.66 39.58,22.46 R8.2 ; R14.2 35.41,22.55 v1(35.09,22.86) 35.32,23.09 36.04,23.09 R14.1 ; R22.2 21.02,46.33 21.05,46.35 v1(21.15,46.35) 21.15,45.81 21.02,45.67 R22.1
  TOP w0.2: v1(35.25,34) 34.7,34 34.67,33.98 34.31,33.98 34.18,33.85 U5.10 ; R4.4 v1(9.8,26.12) ; R5.2 42.9,10.25 42.75,10.4 v1(42.75,11.7) 42.95,11.7 43.4,11.25 R5.1
  TOP w0.25: R13.1 v1(28.55,20.07) ; C10.1 49.78,11.38 U4.11 49.78,13.28 49.85,13.35 v1(49.85,13.38) ; U4.28 59.63,15.08 C11.1 v1(59.75,16) ; v1(33.05,45.1) 32.6,45.1 31.95,44.45 31.8,44.45 L3.1 ; R19.3 31.74,24.44 31.74,24.33 v1(31.75,24.33) ; U4.6 v1(47.28,13.41)
  TOP w0.3: C12.1 v1(58.55,26.75) 58.55,26.75 58.53,26.73 U4.50 ; SW1.2 12.2,50.66 15.46,47.4 22.4,47.4 v1(23.55,46.25) ; U4.75 44.34,27.83 v1(44.05,28.12) ; U4.100 42.23,14.08 42,13.85 C14.1 v3(41.5,12.99) ; v1(48.35,32.55) 48.84,33.04 C46.1 ; L2.2 57.78,9.43 C7.2 v1(58.6,8.8) ; C45.1 59.02,30.13 v1(58.72,30.43) ; U4.19 53.78,11.28 54.4,10.65 ; R11.1 26.93,14.8 v1(26.35,15.38)
  TOP w0.4: v1(32.75,29.25) 32.65,29.15 C23.1 ; Q7.1 66.1,17.5 65.85,17.75 v2(65.85,18.03) ; v1(26.35,15.38) 27.02,16.05 Q4.1 ; 54.4,10.65 54.75,10.65 55.21,10.2 C9.1 v1(55.21,9.44) ; Q4.4 29.45,17.95 v1(29.55,18.05) ; Q9.1 v2(65.25,21.05) ; Q5.1 v2(65.25,13.05)
  TOP w0.5: C13.1 v1(44.05,28.12) ; C42.1 60.74,15.91 v1(60.74,16.43) ; L4.1 42.73,42.7 v1(42.55,42.52) C33.1
  TOP w0.6: C21.1 v3(36.1,18.7)
  TOP w1: v3(31.05,9.5) 29.95,9.5 v3(29.9,9.45) 29.9,8.44 30.48,7.86 J6.2 ; v3(36.06,9.32) 35.93,9.45 v3(35.05,9.45) 35.05,8.44 35.56,7.93 J6.4
  BOTTOM w0.5: J8.1 v1(58.72,30.43)
  vias: v3(36.8,12.15) v3(37.42,11.59) v3(37.92,12.29)
+3V3_MICROSD: length 21.1
  TOP w0.18: 26.43,13.75 R11.3 ; 26.43,13.75 26.43,14.27 ; 26.43,13.75 26.43,13.38 26.61,13.2 R11.4 ; 26.43,14.27 26.45,14.25 R11.2 ; 26.43,14.27 26.35,14.35
  TOP w0.3: 26.35,14.35 25.55,15.15 25.55,16.55 ; 25.55,16.55 C22.1 ; 25.55,16.55 25.55,17.8 26.15,18.4 v1(26.7,18.4)
  TOP w0.4: J9.4 18.05,16.96 v1(18.04,16.95) ; Q4.6 27.6,18 27.2,18.4 v1(26.7,18.4)
  BOTTOM w0.4: v1(26.7,18.4) 26.43,18.68 19.54,18.68 18.04,17.18 v1(18.04,16.95)
+5.0V: length 27.6
  TOP w0.15: 61.23,17.25 v1(61.75,17.25) ; 61.23,17.25 61.2,17.27 R12.3 ; 61.23,17.25 61.2,17.23 60.85,17.23 60.7,17.38 R12.2
  TOP w0.18: C1.1 31.15,14.85
  TOP w0.2: v1(11.9,26.85) 11.45,27.3 R4.6 ; R12.4 v1(61.75,17.25)
  TOP w0.3: D5.A v1(76.05,2.55) ; U1.3 31.5,13.75 31.15,14.1 31.15,14.85 ; v1(11.35,32.15) C6.1 11.25,31.25 U3.5 ; D1.A v1(7.42,20) ; D6.A v1(76.1,19.15) ; D7.A v1(76.05,35.75)
  TOP w0.4: Q9.4 68,22.95 68.08,23.02 v2(68.9,23.02) ; D2.A 59.66,42.66 v1(59.65,42.65) ; v2(68.5,18.73) 68.5,18.83 68.38,18.95 Q7.4 ; v2(68.9,14.55) 68.5,14.95 Q5.4
  L3-PWR w0.254: J7.2 66.18,31.8 ; J7.2 67.55,30.43 ; J7.2 65.01,31.6 ; J7.2 67.35,29.26 ; J7.2 67.35,31.6
  vias: v1(20.5,25.25) v1(20.5,24) v1(20.5,22.75) v1(20.5,21.5) v1(20.5,20.25) v1(21.75,25.25) v1(21.75,24) v1(21.75,22.75) v1(21.75,21.5) v1(21.75,20.25) v1(23,25.25) v1(23,24) v1(23,22.75) v1(23,21.5) v1(23,20.25) v1(24.25,25.25) v1(24.25,24) v1(24.25,22.75) v1(24.25,21.5) v1(24.25,20.25) v1(25.5,25.25) v1(25.5,24) v1(25.5,22.75) v1(25.5,21.5) v1(25.5,20.25) v3(1.7,29.75) v3(1.7,28.9) v3(1.7,28.05) v3(18.5,25.75) v3(18.5,24.75) v3(18.5,23.75) v3(18.5,22.75) v3(18.5,21.75) v3(18.5,20.75) v3(18.5,19.75) v3(19.5,25.75) v3(19.5,24.75) v3(19.5,23.75) v3(19.5,22.75) v3(19.5,21.75) v3(19.5,20.75) v3(19.5,19.75) v3(26.75,25.75) v3(26.75,24.75) v3(26.75,23.75) v3(26.75,22.75) v3(26.75,21.75) v3(26.75,20.75) v3(26.75,19.82) v3(27.75,25.75) v3(27.75,24.75) v3(27.75,23.75) v3(27.75,22.75) v3(27.75,21.75) v3(27.75,20.75) v3(27.75,19.75) v3(30.75,16.25) v3(31.7,16.25) v3(32.25,17.1)
+VIN: length 52.9
  TOP w0.7: J1.1 6.31,5.01 4.2,7.12 4.2,9.95 1.97,12.18 D3.A
  BOTTOM w0.6: J6.8 44.24,1.06 15.19,1.06 11.24,5.01 J1.1
+VIN_PROTECTED: length 34.5
  TOP w0.2: R6.1 6.38,29.8 7.38,28.8 7.85,28.8 8.2,28.45 8.2,24.4 v1(8.75,23.85)
  TOP w0.8: v3(12.8,19.7) 12.8,21.55 C2.1 13.86,21.8 15.25,20.41 U2.3 ; v3(12.8,19.7) v3(13.75,19.7) ; v3(12.8,19.7) v3(11.85,19.7) ; v3(7.55,14.5) v3(7.55,15.55) ; v3(7.55,14.5) D3.C ; v3(7.55,14.5) v3(8.55,14.5)
  BOTTOM w0.15: 11,19.7 10,20.7 10,22.6 v1(8.75,23.85)
  BOTTOM w0.8: v3(7.55,15.55) v3(7.55,14.5) v3(8.55,14.5) 10.45,16.4 10.45,19.15 11,19.7 v3(11.85,19.7) v3(12.8,19.7) v3(13.75,19.7)
GND: length 132.1
  TOP w0.15: R11.5 v1(28.35,12.57) ; v1(60.3,20.85) 60.15,20.7 R12.8
  TOP w0.18: v1(63.1,21.8) Q11.1 ; 56.35,10.22 56.69,10.22 56.85,10.06 56.85,9.74 56.69,9.58 56.35,9.58 ; C7.3 59.97,9.43 v1(60.3,9.76) 59.99,10.07 C7.4 ; Q10.4 64.4,19.55 64.22,19.73 v1(64.19,19.73) ; D8.2 v1(30.3,42.7) ; v1(64.95,22.05) 64.4,22.6 Q11.4 ; v1(63.03,12.3) 63.03,12.31 63.1,12.31 Q6.1 ; Q10.1 v1(62.45,17.05) ; Q6.4 v1(64.4,15.7)
  TOP w0.2: U5.26 v1(38.3,31.27) ; R4.7 11.75,27.8 v1(11.9,27.65) 11.9,28.11 11.66,28.35 R4.8 ; Q2.1 v1(39.02,11.4) ; C25.2 31.4,40.85 31.55,40.99 31.55,41.34 v1(31.57,41.37) ; U5.63 35.1,37.84 34.76,37.5 v1(34.75,37.5) 34.3,37.05 U5.2 ; U5.8 v1(34.52,34.65) ; R5.6 45.35,9.75 45.45,9.65 v1(45.45,9.2) R5.5 ; U5.58 37.1,39.61 ; Q2.4 41.55,9.95 v1(41.55,9.42) ; U5.11 v1(34.52,33.45) ; U5.18 v1(35.1,31.27)
  TOP w0.25: U4.10 v1(49.28,13.93) ; v1(33.4,23.26) 33.54,23.26 33.79,23.51 R19.5 ; R13.3 31.45,19.43 31.45,19.36 v1(31.43,19.34) ; v1(59.75,13.5) C11.2 59.53,14.3 59.25,14.58 U4.27 ; v1(35.04,25.94) 35.24,25.74 Q1.1 ; C17.2 v1(62.1,26.6) ; R19.8 34.29,25.49 34.64,25.14 v1(34.64,24.94) R19.7 ; Q1.4 v1(38.47,24.44) ; C10.2 v1(47.78,11.08)
  TOP w0.254: 55.79,9.48 C9.2 56.43,10.16 ; 34.65,47.1 C27.2 34.65,45.2 ; C30.2 39.18,40.79 ; C30.2 38.5,41.43 ; C30.2 37.82,40.79 ; 40.84,8.31 C44.2 ; C44.2 41.48,8.99 ; C44.2 41.48,7.63 ; 60.55,27.65 C12.2 59.8,28.42 ; 65.01,26.52 J7.6 ; J7.6 67.35,26.52 ; J7.6 67.35,24.18 ; J7.6 67.55,25.35 ; C45.2 60.36,30.81 ; C45.2 60.36,29.45 ; C45.2 61,30.13 ; J9.10 11.75,8.5 ; J9.10 10.8,7.65 ; J9.10 11.75,6.8
  TOP w0.3: C49.2 43.98,34.2 v1(44.19,34.41) 43.73,34.87 C31.2 ; v1(44.85,26.6) 44.92,26.67 45.28,26.67 U4.74 ; v3(41.5,15.61) C14.2 41.67,14.58 U4.99 ; v1(32.27,31) 31.45,31 C36.2 ; C22.2 27,17.45 27.3,17.15 27.3,16.92 v1(27.37,16.85) ; v1(49.54,34.25) 49.54,33.96 49.42,33.84 C46.2 ; 53.74,10.5 v1(53.65,10.5) 54.2,9.95 54.2,9.45 C19.2 ; C35.2 28.24,31.48 27.51,31.48 v1(27.48,31.45) ; U4.20 v1(54.28,13.41) ; C12.2 58.75,27.65 v1(58.51,27.89) ; v1(59.42,11.14) 59.41,11.15 C5.2 ; v1(16,17) 15.85,17.15 J9.6 ; C27.2 v1(35.6,46.15) ; C20.1 v1(7.75,18.25) ; C38.2 32.65,42.65 32.85,42.45 v1(32.85,42.4) ; v1(39.96,29.1) 39.71,29.1 39.29,28.68 C47.2 ; C18.2 v1(46.75,10.2) ; R10.1 v1(7.72,17.25) ; U3.2 v1(7.17,30.6) ; v1(35.35,41.65) R21.2 ; 33.53,40.4 33.42,40.29 C26.2 33.42,39.72 33.84,39.3 33.93,39.3 33.97,39.26 ; v1(39.31,41.11) 39.31,41.05 ; C37.2 v1(40.15,42.4) ; C29.2 v1(29.45,46.2) ; C28.2 v1(30.35,46.2) ; C6.2 v1(11.35,29.65)
  TOP w0.4: C51.2 27.99,29.21 v1(28.6,29.82) 28.32,30.1 C39.2 ; C32.2 30.77,31.48 C36.2 ; C50.2 30.91,33.16 30.91,33.72 v1(30.84,33.79) ; C48.2 44.32,36.07 v1(44.45,36.2) ; v1(28.75,28.75) 29.45,28.75 C23.2 ; C24.2 v1(29.08,34.8) ; J5.5 5.18,21.52
  TOP w0.5: C42.2 60.8,13.15 v1(60.8,12.57) ; v1(43.76,29.81) 43.8,29.81 43.84,29.85 C16.2 ; C13.2 v1(43.15,28.12) ; C33.2 v1(41.65,42.52) ; C34.2 v1(41.8,39.52)
  TOP w0.6: R20.1 v3(21,28.37) ; C41.1 v3(19.45,27.59) ; C21.2 v3(37.45,18.7)
  TOP w0.76: J11.10 v2(75.95,23.05) ; J10.10 v2(75.95,6.47) ; J12.10 v2(75.95,39.63)
  TOP w0.8: v3(13.05,25.45) C2.2 ; C2.2 13.86,23.6 15.25,24.99 U2.1 ; C2.2 12.7,23.25 v3(11.45,23.25) v3(11.45,24.2) ; C43.2 v1(29.75,26.45) ; v1(29.75,26.45) v1(28.9,26.45) ; v1(29.75,26.45) v1(30.6,26.45)
  L2-GND w0.254: J7.6 67.35,26.52 ; J7.6 67.35,24.18 ; J7.6 67.55,25.35 ; J7.6 65.01,26.52
  BOTTOM w0.25: v1(62.1,26.6) 60.47,26.6 J8.7
  BOTTOM w0.3: J8.3 v1(58.66,29.16) ; 58.95,25.35 J8.9 61.4,25.35 61.92,25.88 v1(62.1,25.88) ; J8.5 v1(58.51,27.89)
  vias: v1(33.95,41.6) v1(36.35,36.2) v1(40.4,32.35) v3(6.25,21.3) v3(6.25,20.45) v3(6.25,19.6) v3(32.5,12.7) v3(32.5,11.8) v3(34.3,15.45) v3(34.3,14.55) v3(34.3,13.65)
VCC3A3: length 13.1
  TOP w0.2: U5.1 33.45,38.01 33.05,38.4 33.05,39.24 32.84,39.46 C26.1 32.47,40.13 32.47,40.36 32.45,40.38 32.45,40.66 32.47,40.68 32.47,41.17 32.57,41.27 32.57,41.68 v1(32.61,41.71)
  TOP w0.3: v1(29.05,43.74) 29.05,44.1 C29.1 C28.1 30.8,44.5 30.95,44.65 30.95,44.99 31.16,45.2 L3.2 31.65,45.7 v1(32.1,46.15) C27.1 ; T1.15 v1(25.95,41.62) ; T1.10 v1(25.95,35.27)
VCC18: length 15.7
  TOP w0.18: U5.43 42.87,35.45 C31.1 ; v1(37.15,36.65) 36.7,37.1 U5.59 ; 31.83,34.25 U5.9 ; U5.24 v1(37.5,31.27)
  TOP w0.2: C25.1 31.4,39.05 31.65,38.8 v1(32.2,38.8)
  TOP w0.3: v1(43.29,34.44) 43.4,34.33 C49.1 ; v1(39.36,40.13) 39.28,40.21 C30.1 ; C50.1 30.09,32.92 29.23,32.92 L5.2
  TOP w0.4: C31.1 43.14,34.59 v1(43.29,34.44) ; 31.83,34.25 31.54,34.25 30.99,34.8 C24.1 30.39,34.26 29.99,33.86 29.95,33.86 v1(29.93,33.89) 29.93,33.83 30.19,33.57 C50.1
VCC18A: length 7
  TOP w0.15: v1(34.6,35.7) 34.52,35.78 34.5,35.78 34.43,35.85 U5.5
  TOP w0.18: v1(35.97,37.4) 36.3,37.73 U5.60
  TOP w0.3: L5.1 29.06,32.19 28.37,32.19 C35.1 ; C36.1 v1(28.8,30.9)
  TOP w0.4: L5.1 29.18,32.13 C32.1 30.19,31.34 C36.1
VCCIO: length 6.6
  TOP w0.18: U5.25 v1(37.9,29.12) ; U5.44 42.92,35.85 C48.1 43.18,36.11 43.18,36.48 43.31,36.61
  TOP w0.25: 43.31,36.61 v1(43.31,36.83)
  TOP w0.3: v1(37.9,29.12) 38.38,28.64 C47.1
  TOP w0.5: L4.2 43.6,40.7 C34.1 v1(43.4,39.52)
VDDA: length 7
  TOP w0.3: U4.21 54.78,11.38 54.96,11.2 55.28,11.2 ; 55.28,11.2 55.33,11.15 C5.1 57.7,11.1 L2.1 57.85,10.1 58.57,10.1 C7.1 ; 55.28,11.2 U4.22
VIN_COMP: length 6.2
  TOP w0.15: R4.1 9.16,28.35 9,28.51 9,28.75 8.8,28.95 8.8,30.9 8.45,31.25 U3.1 7.08,31.25 6.83,31 6.65,31 R6.2
VIN_COMP_LOGIC: length 10.1
  TOP w0.15: U3.4 10.05,29.95 9.45,30.55 9.45,31.66 9.22,31.88 9.03,32.08 6.99,32.08 6.62,31.71 5.63,31.71 4.67,30.76 4.67,30.18 4.3,29.8 Q3.1
VIN_REF: length 4.5
  TOP w0.2: R4.2 9.01,27.8 9,27.81 ; U3.3 8.1,29.1 8.65,28.55 8.65,28.16 9,27.81 ; 9,27.81 9,27.5 9.2,27.3 R4.3
/AX_CS: length 18.9
  TOP w0.15: U4.65 49.78,29.07 48.96,29.07 47.81,30.22 47.81,31.13 45.84,33.11 45.84,35.7 42.88,38.65 41.95,38.65 40.9,39.7 39.62,39.7 39.5,39.58 U5.52
/AX_INT: length 29.1
  TOP w0.15: U4.29 56.94,15.58 56.41,16.11 55.92,16.11 54.65,17.38 54.25,17.38 53.43,18.2 53.43,19.06 52.15,20.35 52.15,20.48 50.63,22 46.71,22 44.61,24.1 v1(44.08,24.1)
  TOP w0.18: U5.23 v1(37.1,29.12)
  BOTTOM w0.15: v1(37.1,29.12) 38.33,27.9 38.55,27.9 41.25,25.2 41.25,24.54 41.69,24.1 v1(44.08,24.1)
/AX_RESET: length 70.7
  TOP w0.15: v1(42.58,9.45) 42.88,9.75 R5.3 ; U4.37 v1(55.98,19.58)
  TOP w0.18: U5.17 v1(34.7,29.12)
  L2-GND w0.15: v1(34.7,29.12) 35.59,29.12 36.09,29.62 41.09,29.62 43.52,32.05 45.91,32.05 46.52,31.44 46.52,27.18 45.24,25.89 38.56,25.89 37.51,24.84 37.34,24.67 37.34,21.14 39.65,18.83 39.65,11.42 40.57,10.5 41.53,10.5 v1(42.58,9.45)
  BOTTOM w0.15: v1(55.98,19.58) 55.98,18.88 56.18,18.68 56.18,18.27 55.86,17.95 52.92,17.95 52.62,17.65 51.32,17.65 49.51,15.84 48.64,15.84 48,15.2 45.3,15.2 44.25,14.15 44.25,11.12 v1(42.58,9.45)
/ENABLE_UART_TX_PULLUP_GOPORT1: length 41
  TOP w0.15: R14.8 37.2,23.15 37.2,23.4 37,23.6 35.12,23.6 32.7,21.18 32.7,19.06 31.09,17.45 v1(30.5,17.45) 29.22,17.45 29.19,17.43 29.02,17.43 28.94,17.35 28.4,17.35 28.25,17.5 Q4.5 ; U4.2 45.28,11.48 44.56,11.48 43.55,12.5 41.79,12.5 41.73,12.44 38.93,12.44 38.23,11.73 38.23,11.2 37.65,10.62 28.95,10.62 v1(28.57,10.25)
  BOTTOM w0.15: v1(30.5,17.45) 29.85,16.8 29.85,16.5 28.75,15.4 28.75,12.88 28.85,12.78 28.85,12.11 28.57,11.83 v1(28.57,10.25)
/ENABLE_UART_TX_PULLUP_GOPORT2: length 42.6
  TOP w0.15: Q8.2 48.85,31.15 49,31.3 49,31.46 49.1,31.56 v1(49.1,32) ; R14.7 38.45,22.55 v1(38.7,22.3) ; v1(53.85,21.05) 53.85,21.15 54.28,21.58 U4.41
  L2-GND w0.15: v1(49.1,32) 49.46,32 50,31.46 50,30.9 49.15,30.05 49.15,26.98 48.45,26.28 47.35,26.28 46.4,25.33 46.4,24.95 45.05,23.6 43.89,23.6 43.6,23.31 43.6,22.75 ; v1(51.75,19.85) 50.81,19.85 50.61,20.06 49.85,20.06 49.36,20.55 47.95,20.55 46.95,19.55 45.79,19.55 45.5,19.84 45.5,20.94 44.24,22.2 44.15,22.2 43.6,22.75 ; 43.6,22.75 41.1,22.75 40.75,22.4 40.75,21.05 40.4,20.7 40,20.7 39.25,21.45 39.25,21.75 v1(38.7,22.3)
  BOTTOM w0.15: v1(51.75,19.85) 52.95,21.05 v1(53.85,21.05)
/ENABLE_UART_TX_PULLUP_GOPORT3: length 39.9
  TOP w0.15: v1(44.1,21.55) 44.3,21.55 44.35,21.5 50.4,21.5 51.25,20.65 v1(51.25,20.45) ; U4.43 55.28,22.58 54.58,21.88 54.11,21.88 53.92,21.7 v1(53.4,21.7) ; v1(49.5,31.25) 49.6,31.15 Q8.5 ; v1(40.22,21.23) 39.17,21.23 38.7,21.7 38.59,21.7 38.24,22.05 R14.6
  L2-GND w0.15: v1(49.5,31.25) 48.98,31.25 47.48,29.76 47.48,27.27 45.12,24.9 43.25,24.9 42.6,24.25 41.89,24.25 40.22,22.58 v1(40.22,21.23)
  BOTTOM w0.15: v1(44.1,21.55) 42.55,21.55 41.95,20.95 41.2,20.95 40.92,21.23 v1(40.22,21.23) ; v1(53.4,21.7) 52.5,21.7 v1(51.25,20.45)
/EXTERNAL_RESET: length 119
  TOP w0.15: 41.05,10.75 Q2.5 ; 41.05,10.75 40.75,10.45 40.75,10.23 40.19,9.68 36.8,9.68 36.18,10.3 33.02,10.3 ; 41.05,10.75 40.9,10.9 v1(40.9,11.3) ; v1(66.95,4.9) 63.05,4.9 62.51,5.45 v1(48.16,5.45) ; J6.3 33.02,10.3 ; 33.02,10.3 29.35,10.3 28.75,9.7 26.6,9.7 21.65,14.65 16.65,14.65 15.5,15.8 v1(14.95,15.8)
  TOP w0.2: v1(9.45,24.05) 9.45,24.7 11,26.25 R4.5
  L2-GND w0.15: J7.5 65.06,23.93 65.65,23.93 65.75,23.83 67.55,23.83 69.1,25.38 69.1,26.25 70.05,27.2 70.5,27.2 70.9,26.8 70.9,23.85 69.8,22.75 69.8,19.14 72.9,16.04 72.9,8.9 68.9,4.9 v1(66.95,4.9) ; v1(40.9,11.3) 42.3,11.3 v1(48.16,5.45)
  BOTTOM w0.15: v1(9.45,24.05) 13.18,20.32 14.01,20.32 14.95,19.38 v1(14.95,15.8)
/INT_GOPORT1: length 34.4
  TOP w0.15: v1(70.35,11.5) 70.49,11.36 J10.3 ; U4.60 52.28,28.86 52.26,28.86 v1(52.26,28.88)
  L2-GND w0.15: v1(70.35,11.5) 69.47,12.38 68.62,12.38 68.22,12.77 68.22,12.93 64.8,16.35 61.85,16.35 59.22,18.98 55.34,18.98 54.97,19.35 53.15,19.35 50.95,21.55 50.95,25.45 52.26,26.76 v1(52.26,28.88)
/INT_GOPORT2: length 30
  TOP w0.15: v1(51.53,28.92) 51.78,28.67 U4.61 ; J11.3 71.79,28.2 70.35,28.2 68.5,30.05 68.5,30.75 66.2,33.05 62.05,33.05 60.29,31.29 58.66,31.29 57.5,30.13 57.5,27.25 57,26.75 v1(54.8,26.75)
  L2-GND w0.15: v1(54.8,26.75) 53.05,28.5 53.05,28.8 52.47,29.38 51.98,29.38 v1(51.53,28.92)
/INT_GOPORT3: length 32.1
  TOP w0.15: v1(68.88,44.83) 69.4,44.83 69.7,44.52 J12.3 ; U4.62 51.28,26.86 v1(51.21,26.78)
  BOTTOM w0.15: v1(51.21,26.78) 51.21,28.04 51.03,28.22 51.03,29.71 54.68,33.36 54.68,34.36 59.06,38.73 59.33,39 62.25,39 68.08,44.83 v1(68.88,44.83)
/LINK_ACT: length 40
  TOP w0.18: D9.3 2.4,50.9 2.55,51.05 3.65,51.05 4.15,50.55 7,50.55 10.56,46.98 v1(12.21,46.98) ; U5.14 v1(32.38,32.25)
  BOTTOM w0.15: v1(32.38,32.25) 32.27,32.35 31.54,32.35 31.49,32.3 30.81,32.3 29.16,33.95 28.42,33.95 27.95,34.42 27.95,35.25 16.21,46.98 v1(12.21,46.98)
/MICRO_SD_CARD_INSERTED: length 54.6
  TOP w0.15: v1(44.14,20.83) 44.78,20.83 45.1,21.15 49.9,21.15 49.93,21.12 50.06,21.12 v1(50.43,20.75) ; U4.48 56.89,25.08 55.01,23.21 53.16,23.21 v1(52.71,22.75)
  TOP w0.18: J9.9 12.75,18.1 v1(12.75,16.8) ; v1(31.6,20.05) 30.62,20.05 R13.4
  BOTTOM w0.15: v1(12.75,16.8) 13.35,16.8 14.15,16 14.15,15.47 14.62,15 18.95,15 19.13,15.18 19.87,15.92 19.87,16.48 19.86,16.49 19.86,16.91 20.15,17.2 20.57,17.2 20.62,17.15 23.99,17.15 24.24,16.9 25.85,16.9 26.25,17.3 27.16,17.3 27.21,17.35 27.75,17.35 28.95,18.55 29.85,18.55 31.35,20.05 v1(31.6,20.05) 32.2,20.65 43.44,20.65 43.61,20.83 v1(44.14,20.83) ; v1(52.71,22.75) 51.76,21.8 51.48,21.8 v1(50.43,20.75)
/MICROSD_CS: length 43.7
  TOP w0.15: U4.35 57.33,18.58 57.32,18.59 56.34,18.59 56.22,18.48 v1(55.68,18.48)
  TOP w0.18: v1(20.36,16.7) 20.36,17.14 20.25,17.25 J9.2
  BOTTOM w0.15: v1(20.36,16.7) 24.02,16.7 24.37,16.35 27.74,16.35 28.94,17.55 29.76,17.55 30.61,18.4 32.16,18.4 33.06,17.5 44.45,17.5 46.15,15.8 47.75,15.8 48.39,16.44 49.24,16.44 51.06,18.25 52.37,18.25 53.41,19.28 55.04,19.28 55.33,18.99 55.33,18.83 v1(55.68,18.48)
/PWR_CTRL_GOPORT1: length 15.3
  TOP w0.15: R12.7 60.7,20.09 60.67,20.12 v1(60.67,20.12) ; Q5.5 Q5.2 66.75,12.5 66.5,12.25 64.64,12.25 64.4,12.48 Q6.3 64.4,13.95 v1(64.35,14)
  BOTTOM w0.15: v1(60.67,20.12) 60.67,19.47 62.29,17.85 62.78,17.85 63.6,17.03 63.6,15.37 64.22,14.74 64.22,14.53 64.35,14.4 v1(64.35,14)
/PWR_CTRL_GOPORT2: length 14.1
  TOP w0.15: Q6.6 63.1,15.5 63.85,16.25 66.5,16.25 66.75,16.5 Q7.2 Q7.5 66.75,19.52 66.19,20.07 64.58,20.07 64.43,20.23 63.94,20.23 63.62,19.9 61.35,19.9 61.2,19.75 R12.6
/PWR_CTRL_GOPORT3: length 12.9
  TOP w0.15: R12.5 61.75,19.1 63.15,17.7 64.3,17.7 64.4,17.6 ; Q9.2 v1(66.75,21.9) Q9.5 ; 64.4,17.6 v1(64.8,18) ; 64.4,17.6 Q10.3
  BOTTOM w0.15: v1(66.75,21.9) 66.22,21.38 66.22,21.07 65.45,20.3 64.06,20.3 63.69,19.93 63.69,19.49 64.8,18.37 v1(64.8,18)
/PWR_CTRL_MICROSD: length 35.4
  TOP w0.15: v1(54.83,18.78) 55.13,19.08 U4.36
  TOP w0.18: Q4.2 28.25,15.34 28.35,15.24 R11.8 29.1,14.8 v1(29.25,14.95)
  BOTTOM w0.15: v1(29.25,14.95) 30.18,15.88 30.18,16.46 30.66,16.95 31.1,16.95 31.81,17.66 32.48,17.66 32.94,17.2 43.9,17.2 45.6,15.5 47.88,15.5 48.51,16.14 49.39,16.14 51.2,17.95 52.5,17.95 53.33,18.78 v1(54.83,18.78)
/RESET_MCU: length 42.5
  TOP w0.15: 42.08,8.32 42.08,9.66 42.35,9.93 42.35,11.2 42.15,11.4 Q2.6 ; 42.08,8.32 C44.1 ; 42.08,8.32 42.08,8.3 42.72,7.65 44.61,7.65 45.95,8.99 45.95,9.95 v1(45.62,10.28) 44.62,10.28 R5.7 ; U4.14 51.28,13.18 51.06,13.4 50.54,13.4 50,13.94 v1(50,14.35) 50.54,14.35 50.79,14.6 52.7,14.6 52.88,14.42 v1(53.62,14.42)
  BOTTOM w0.15: v1(45.62,10.28) 48.77,13.42 48.77,14.12 49.07,14.43 49.92,14.43 v1(50,14.35) ; v1(53.62,14.42) 54.16,14.42 54.29,14.55 55.5,14.55 55.5,17.16 56.48,18.14 56.48,19.96 52.45,23.99 52.45,24.41 53.07,25.03 53.22,25.03 53.54,25.35 J8.10
/SPEED: length 38.5
  TOP w0.18: D9.4 3.56,50.35 3.77,50.15 6.85,50.15 10.65,46.35 v1(11.8,46.35) ; v1(31.75,31.85) 31.86,31.73 32.59,31.73 32.7,31.85 U5.15
  BOTTOM w0.15: v1(31.75,31.85) 30.83,31.85 29.03,33.65 28.55,33.65 28.3,33.65 27.65,34.3 27.65,35.03 16.33,46.35 v1(11.8,46.35)
/SPI_CS_GOPORT1: length 70.9
  TOP w0.15: v1(74.28,9.8) 74.56,10.09 J10.6 ; v1(41.73,19.51) 41.47,19.25 40.94,19.25 40.65,18.96 40.65,17.2 40.85,17 40.91,17 41.2,16.71 41.2,16.09 40.94,15.84 40.94,14.79 v1(40.57,14.42) ; v1(44.59,22.56) 44.55,22.6 44.55,22.84 44.6,22.89 44.6,23.31 44.31,23.6 43.9,23.6 43.88,23.58 U4.81
  BOTTOM w0.15: v1(40.57,14.42) 40.57,12.02 40.4,11.85 40.4,9.4 41.15,8.65 42.91,8.65 43.14,8.65 43.43,8.36 43.43,6.87 44.6,5.7 44.9,5.7 49.31,1.29 70.9,1.29 74.28,4.67 v1(74.28,9.8) ; v1(41.73,19.51) 43.99,19.51 44.9,20.42 44.9,20.51 45.9,21.51 45.9,22.55 44.85,23.6 43.89,23.6 43.6,23.31 43.6,22.89 43.93,22.56 v1(44.59,22.56)
/SPI_CS_GOPORT2: length 86.3
  TOP w0.15: U4.82 43.78,23.08 43.8,23.1 v1(44.1,23.1) ; v1(63.7,5.45) 62.95,6.2 44.95,6.2 v1(44,7.15) ; v1(40.7,16.5) 40.2,17 37.75,17 36.75,18 36.75,19.5 37.4,20.15 v1(41.35,20.15) ; J11.6 v1(74.3,26.67)
  BOTTOM w0.15: v1(40.7,16.5) 41.39,16.5 41.69,16.2 43.2,16.2 43.9,15.5 43.9,11.48 42.08,9.66 42.08,9.24 42.37,8.95 42.78,8.95 42.78,8.95 43.26,8.95 44,8.21 v1(44,7.15) ; v1(63.7,5.45) 65.82,5.45 65.83,5.45 66.25,5.45 66.28,5.45 70.3,5.45 73.5,8.65 73.5,9.73 74.36,10.59 74.36,12.16 75.75,13.55 75.75,14.19 75.35,14.59 75.35,22.35 74.3,23.4 v1(74.3,26.67) ; v1(44.1,23.1) 44.93,23.1 45.6,22.43 45.6,21.63 44.6,20.63 44.6,20.54 44.21,20.15 v1(41.35,20.15)
/SPI_CS_GOPORT3: length 59.4
  TOP w0.15: U4.83 43.87,22.58 44.4,22.05 v1(45.1,22.05) ; v1(58.65,34.35) 67,42.7 67,43.96 70.59,47.55 72.81,47.55 73.85,46.5 73.85,43.65 74.25,43.25 J12.6
  L2-GND w0.15: v1(45.1,22.05) 45.62,22.05 46.85,23.28 46.85,25.36 47.47,25.98 48.58,25.98 50.7,28.1 50.7,29.27 51.05,29.62 51.05,33.2 50.55,33.7 50.55,36 49.65,36.9 49.65,37.61 49.94,37.9 55.11,37.9 55.7,37.31 55.7,37.3 v1(58.65,34.35)
A0: length 13.5
  TOP w0.18: U4.15 51.78,13.2 51.18,13.8 50.95,13.8 v1(50.85,13.9)
  BOTTOM w0.15: v1(50.85,13.9) 50.85,3.85 50.8,3.81 J4.1
A1: length 14.2
  TOP w0.18: U4.16 52.28,13.57 v1(51.75,14.1)
  BOTTOM w0.15: J4.2 51.75,4.13 v1(51.75,14.1)
A2: length 15.3
  TOP w0.18: U4.17 v1(52.78,13.82)
  BOTTOM w0.15: J4.3 54.57,3.85 53.25,3.85 52.25,4.85 52.25,13.29 v1(52.78,13.82)
A3: length 17.2
  TOP w0.18: v1(53.59,13.69) 53.59,13.69 53.28,13.37 U4.18
  BOTTOM w0.15: J4.4 56.71,4.25 53.55,4.25 52.75,5.05 52.75,12.85 v1(53.59,13.69)
A4: length 18.8
  TOP w0.15: v1(56.6,17.56) 57.28,17.56 57.31,17.58 U4.33
  BOTTOM w0.15: J4.5 59.78,3.71 59.78,8.61 56.6,11.8 v1(56.6,17.56)
A5: length 20.2
  TOP w0.15: U4.34 57.64,18.08 57.63,18.09 v1(57.09,18.09)
  BOTTOM w0.15: J4.6 62.09,3.95 61.1,3.95 60.15,4.9 60.15,8.71 57.1,11.76 57.1,17.35 57.1,17.35 57.1,18.08 v1(57.09,18.09)
AX_MISO: length 29.3
  TOP w0.15: v1(48.17,25.2) 48.62,24.75 49.08,24.75 49.25,24.58 49.69,24.58 49.72,24.61 50.26,24.61 51.31,23.57 51.31,22.67 51.31,22.17 52.75,20.73 52.75,20.59 54.03,19.31 54.03,18.45 54.5,17.98 54.98,17.98 56.21,16.76 56.69,16.76 56.87,16.58 U4.31
  TOP w0.18: v1(40.55,34.6) 40.6,34.65 U5.41
  BOTTOM w0.15: v1(48.17,25.2) 48.17,26.15 47.55,26.77 47.55,27.6 v1(40.55,34.6)
AX_MOSI: length 28.9
  TOP w0.15: v1(49,25.25) 49.37,24.88 49.57,24.88 49.6,24.91 50.39,24.91 51.61,23.69 51.61,22.54 51.61,22.29 53.05,20.85 53.05,20.72 54.33,19.44 54.33,18.57 54.62,18.28 55.15,18.28 56.37,17.06 56.81,17.06 56.83,17.08 U4.32
  TOP w0.18: U5.42 41.09,35.05 v1(40.9,35.23)
  BOTTOM w0.15: v1(49,25.25) 48.75,25.5 48.75,26.99 47.98,27.75 47.92,27.75 41.28,34.38 41.28,34.85 v1(40.9,35.23)
AX_SCK: length 33.4
  TOP w0.15: v1(47.45,25.25) 47.45,25.21 49.36,23.3 50.7,23.3 51.01,22.99 51.01,22.79 51.01,22.05 52.45,20.6 52.45,20.47 53.73,19.19 53.73,18.33 54.38,17.68 54.81,17.68 56.06,16.44 56.55,16.44 56.9,16.08 U4.30
  TOP w0.18: v1(39.8,34.5) 39.8,35.5 38.34,36.96 38.34,37.62 37.9,38.06 U5.56
  BOTTOM w0.15: v1(47.45,25.25) 46.15,26.55 46.15,28.15 v1(39.8,34.5)
AX_WAKE_UP: length 27.7
  TOP w0.15: v1(46.7,16.3) 45.78,15.38 U4.3
  TOP w0.18: U5.22 36.7,31.2 36.98,31.48 36.98,31.49 37.29,31.79 37.29,31.79 v1(37.95,32.45)
  BOTTOM w0.15: v1(37.95,32.45) 38.32,32.08 38.32,31.96 40.71,29.57 40.71,28.58 42.99,26.3 43.86,26.3 46.36,23.8 47.1,23.06 47.1,17.23 46.7,16.82 v1(46.7,16.3)
CHASSIS_ETHERNET: length 4.6
  TOP w0.3: R20.2 20.6,30.5 C41.2 19.3,30.5 18.7,31.1 C40.2
CHASSIS_USB: length 32.2
  TOP w0.3: D4.2 7.05,21.74 7.35,21.44 v3(7.5,21.44) ; 4.15,18.25 J5.7 ; 4.15,18.25 C20.2 ; 4.15,18.25 4.15,17.85 4.75,17.25 R10.2
  BOTTOM w0.254: 4.15,24.17 J5.6 ; J5.6 3.21,24.17 ; J5.6 3.21,26.47 ; J5.6 5.09,24.17 ; J5.6 4.15,26.47 ; J5.6 3.13,25.32 ; 3.13,20.32 J5.7 ; J5.7 4.15,21.47 ; J5.7 3.21,21.47 ; J5.7 4.15,19.17 ; J5.7 3.21,19.17 ; 1.25,26.18 2.55,26.18 ; 1.25,26.18 1.25,25.07 ; 1.25,26.18 2.55,25.17 ; 1.25,26.18 0.6,25.12 ; J5.11 1.25,20.57 ; J5.11 2.55,20.47 ; J5.11 2.55,19.46 ; J5.11 1.9,20.52
D0: length 35.9
  TOP w0.15: U4.64 50.28,28.81 51.19,29.72 52.55,29.72 53.04,29.24 53.86,29.24 54.7,30.08 54.7,31.21 53.95,31.96 53.95,34.96 52.1,36.81 52.1,44.7 55,47.59 60.3,47.59 J2.1
D1: length 35.2
  TOP w0.15: U4.63 50.78,28.89 51.32,29.42 52.43,29.42 52.91,28.94 53.98,28.94 55,29.96 55,31.33 54.43,31.9 54.43,34.9 52.4,36.93 52.4,44.58 55.09,47.27 60.81,47.27 v1(61.25,47.7)
  BOTTOM w0.15: v1(61.25,47.7) 61.25,49.24 60.96,49.53 J2.2
D2: length 47.3
  TOP w0.15: v1(52.25,18.9) 54.07,17.08 54.48,17.08 55.79,15.78 55.99,15.78 57.68,14.08 U4.26
  BOTTOM w0.15: J2.3 58.42,38.76 54.35,34.69 54.35,33.45 50.71,29.81 50.71,26.07 50.73,26.04 50.73,25.38 48.65,23.3 48.65,20.26 48.65,19.84 49.59,18.9 v1(52.25,18.9)
D3: length 48.8
  TOP w0.15: U4.25 56.78,13.24 55.49,14.52 55.22,14.52 53.91,15.82 51.88,15.82 v1(49.9,17.8)
  BOTTOM w0.15: J2.4 58,48.68 58,38.77 54.05,34.82 54.05,34.42 49.69,30.06 49.69,29.51 50.41,28.79 50.41,25.94 50.43,25.92 50.43,25.5 48.35,23.42 48.35,20.48 48.35,19.35 v1(49.9,17.8)
D4: length 28.6
  TOP w0.15: v1(57.5,46.5) 57.5,45.73 53.6,41.83 53.6,37.43 57.1,33.93 57.1,32.95 56.78,32.63 U4.51
  BOTTOM w0.15: v1(57.5,46.5) 57.5,47.85 56.25,49.1 55.04,49.1 J2.5
D5: length 48.5
  TOP w0.15: J2.6 50.8,37.21 51.55,36.46 51.55,36.04 51.26,35.75 49.8,35.75 v1(46.85,32.8) ; v1(41.9,16.7) 41.94,16.65 42.11,16.65 42.18,16.58 U4.95
  L2-GND w0.15: v1(41.9,16.7) 41.53,17.07 40.48,17.07 39.95,17.6 39.95,18.95 37.64,21.26 37.64,24.54 38.68,25.59 45.38,25.59 46.85,27.06 v1(46.85,32.8)
D6: length 40.2
  TOP w0.15: U4.96 43.88,16.08 46,18.2 v1(46,20.05) ; J2.7 48.26,39.04 49.53,37.77 49.78,37.77 v1(50.15,37.4)
  L2-GND w0.15: v1(46,20.05) 49.5,23.55 49.5,25.43 49.43,25.5 49.43,26.28 51,27.85 51,29.15 51.35,29.5 51.35,33.32 50.85,33.82 50.85,36.6 50.35,37.1 50.35,37.25 50.2,37.4 v1(50.15,37.4)
D7: length 51.4
  TOP w0.15: U4.24 56.28,13.28 55.34,14.22 55.1,14.22 53.82,15.49 51.48,15.49 49.39,17.58 v1(49.21,17.58)
  TOP w0.18: J2.8 42.75,47.83 v1(42.75,44.1)
  BOTTOM w0.15: v1(49.21,17.58) 48.05,18.74 48.05,20.6 48.05,23.55 45.8,25.8 45.8,26.86 45.26,27.4 43.17,27.4 42,28.57 42,29.85 39.55,32.3 39.55,33.53 39,34.08 39,34.83 41.15,36.98 41.15,42.73 41.77,43.35 42,43.35 v1(42.75,44.1)
D8: length 50.2
  TOP w0.15: v1(48.87,16.94) 49.57,16.94 51.34,15.16 53.72,15.16 54.97,13.92 55.18,13.92 55.78,13.32 U4.23
  TOP w0.18: v1(41.99,44.23) 41.99,47.01 41.66,47.34 J3.1
  BOTTOM w0.15: v1(48.87,16.94) 48.25,17.56 48.25,18.11 47.75,18.61 47.75,20.72 47.75,23.26 46.61,24.4 45.45,25.56 45.45,26.71 45.06,27.1 43.04,27.1 41.67,28.47 41.67,29.71 39.22,32.16 39.22,33.43 38.7,33.95 38.7,34.96 40.85,37.11 40.85,43.09 v1(41.99,44.23)
D9: length 46.4
  TOP w0.15: J3.2 39.12,49.18 41.4,46.9 v1(41.4,44.65) ; v1(47.42,16.36) 47.42,15.67 46.28,14.53 U4.4
  BOTTOM w0.15: v1(47.42,16.36) 47.95,16.89 47.95,17.99 47.45,18.49 47.45,20.85 47.45,23.14 46.49,24.1 43.89,26.7 43.02,26.7 41.2,28.52 41.2,29.51 38.7,32.01 38.7,33.53 38.4,33.83 38.4,35.42 40.37,37.39 40.37,41.47 39.65,42.19 39.65,42.9 v1(41.4,44.65)
D10: length 54.6
  TOP w0.15: J3.3 40.9,46.48 40.9,44.44 41.74,43.6 v1(46.3,43.6) ; U4.47 56.81,24.58 54.48,22.25 52.5,22.25 52.21,22.54 52.21,24.14 50.64,25.71 v1(49.93,25.71)
  BOTTOM w0.15: v1(49.93,25.71) 49.93,28.72 49.39,29.26 49.39,30.18 53.75,34.54 53.75,34.94 55.7,36.89 55.7,41.25 53.35,43.6 v1(46.3,43.6)
D11: length 58.3
  TOP w0.15: 55.3,32 55.3,31.5 55.35,31.45 55.35,28.84 55.28,28.77 U4.54 ; 55.3,32 v1(55.3,32) ; 55.3,32 55.27,32.03 55.27,34.49 52.7,37.06 52.7,43.42 55.1,45.82 v1(55.1,46.47)
  BOTTOM w0.15: J7.4 64.91,29.16 62.6,29.16 62.38,29.39 62.38,31.44 60.7,33.12 57.42,33.12 56.3,32 v1(55.3,32) ; J3.4 38.37,46.47 v1(55.1,46.47)
D12: length 56.5
  TOP w0.15: U4.53 55.78,31.77 55.8,31.79 55.8,32.89 55.79,32.89 v1(55.79,33.42) 55.79,34.39 53,37.18 53,43.19 v1(55.78,45.97)
  BOTTOM w0.15: J7.1 63.62,30.43 62.95,31.1 62.95,31.6 60.7,33.85 56.22,33.85 v1(55.79,33.42) ; J3.5 32.9,49.4 34.45,49.4 37.88,45.97 v1(55.78,45.97)
D13: length 65.5
  TOP w0.15: U4.52 56.28,32.84 56.6,33.16 v1(56.6,33.23) 56.6,34 53.3,37.3 53.3,42.24 v1(56.46,45.4)
  BOTTOM w0.15: J3.6 30.76,49 33.85,49 37.45,45.4 v1(56.46,45.4) ; J7.3 62.7,28.84 62.5,28.84 62.05,29.29 62.05,31.35 60.58,32.82 57.54,32.82 56.23,31.5 55.09,31.5 54.8,31.79 54.8,32.21 55.45,32.86 56.23,32.86 v1(56.6,33.23)
JTCK: length 15.2
  TOP w0.15: v1(52.77,26.13) 52.24,26.13 52.09,26.28 51,26.28 50.77,26.51 48.82,26.51 48.39,26.08 U4.76
  BOTTOM w0.15: J8.4 55.73,29.16 55.73,29.09 v1(52.77,26.13)
JTDI: length 16.3
  TOP w0.15: v1(50.43,22.8) 48.4,22.8 45.62,25.58 U4.77
  BOTTOM w0.15: J8.8 55.73,26.62 55.17,26.06 53.83,26.06 53.1,25.33 52.9,25.33 50.8,23.23 50.8,23.17 v1(50.43,22.8)
JTDO: length 20.7
  TOP w0.15: U4.89 44.82,19.58 45.79,20.55 49.41,20.55 v1(50.4,19.56)
  BOTTOM w0.15: v1(50.4,19.56) 50.4,20.08 49.9,20.58 49.9,23.25 51.65,25 52.15,25 52.78,25.63 52.97,25.63 53.6,26.25 53.6,26.26 55.23,27.89 J8.6
